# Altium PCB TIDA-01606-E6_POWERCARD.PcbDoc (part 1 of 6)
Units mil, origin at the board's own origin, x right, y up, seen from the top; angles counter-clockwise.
Board outline 13779.53 x 7874.02 mil, 4 copper layers (Top Layer, Gnd Layer, Pwr Layer, Bottom Layer), stack 94.4 mil thick; 550 components, 292 nets, 1594 pads, 572 vias.
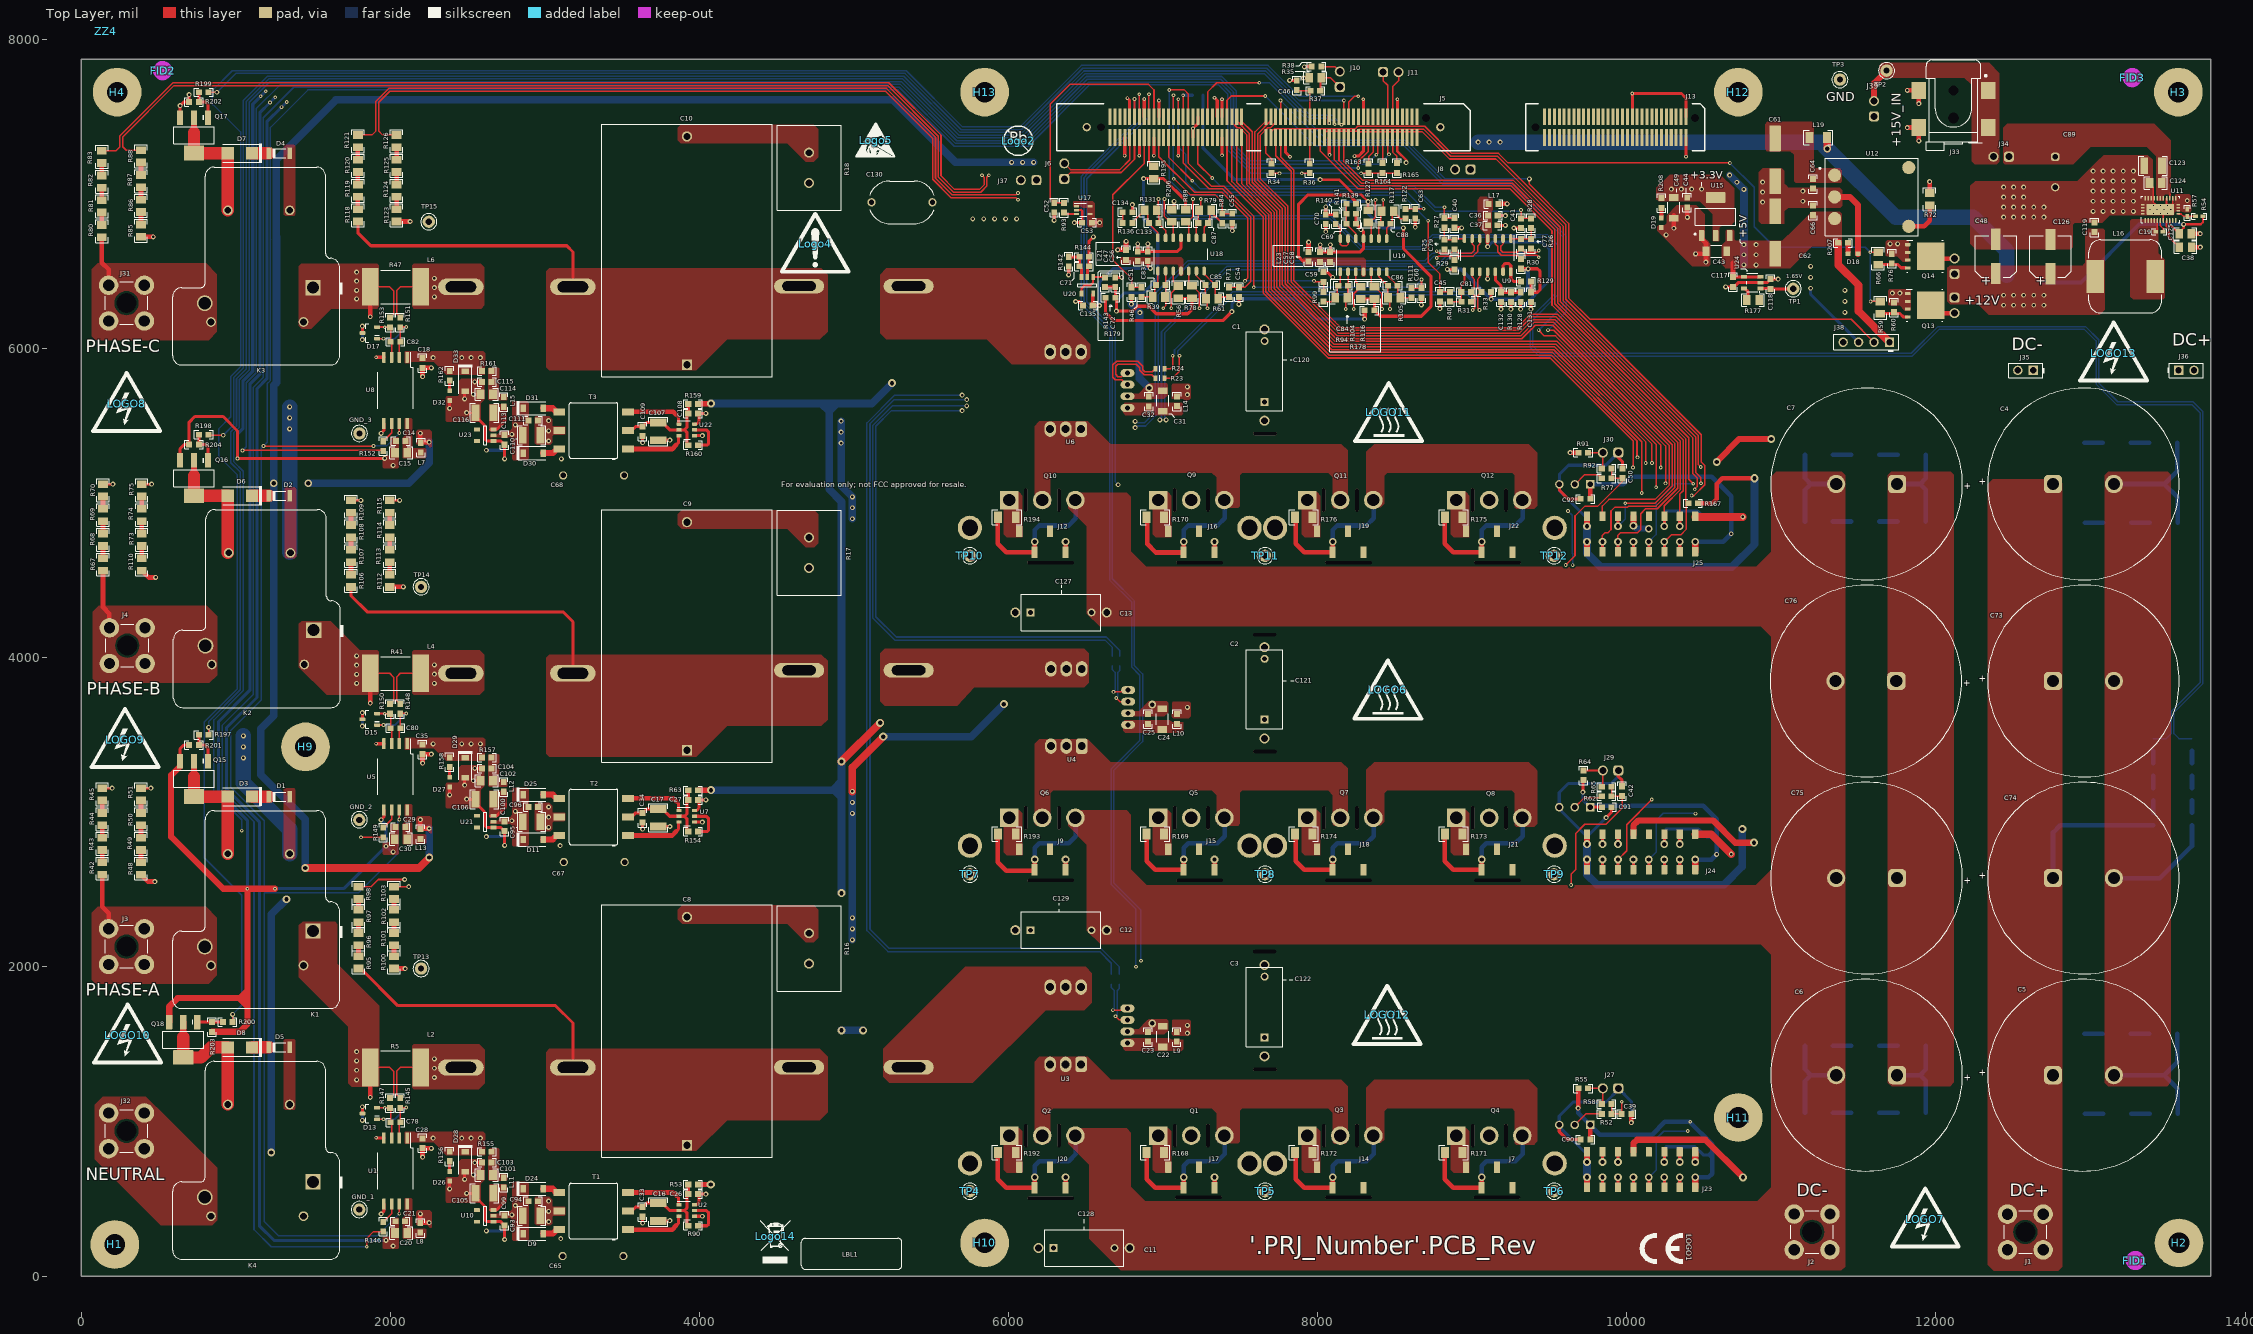
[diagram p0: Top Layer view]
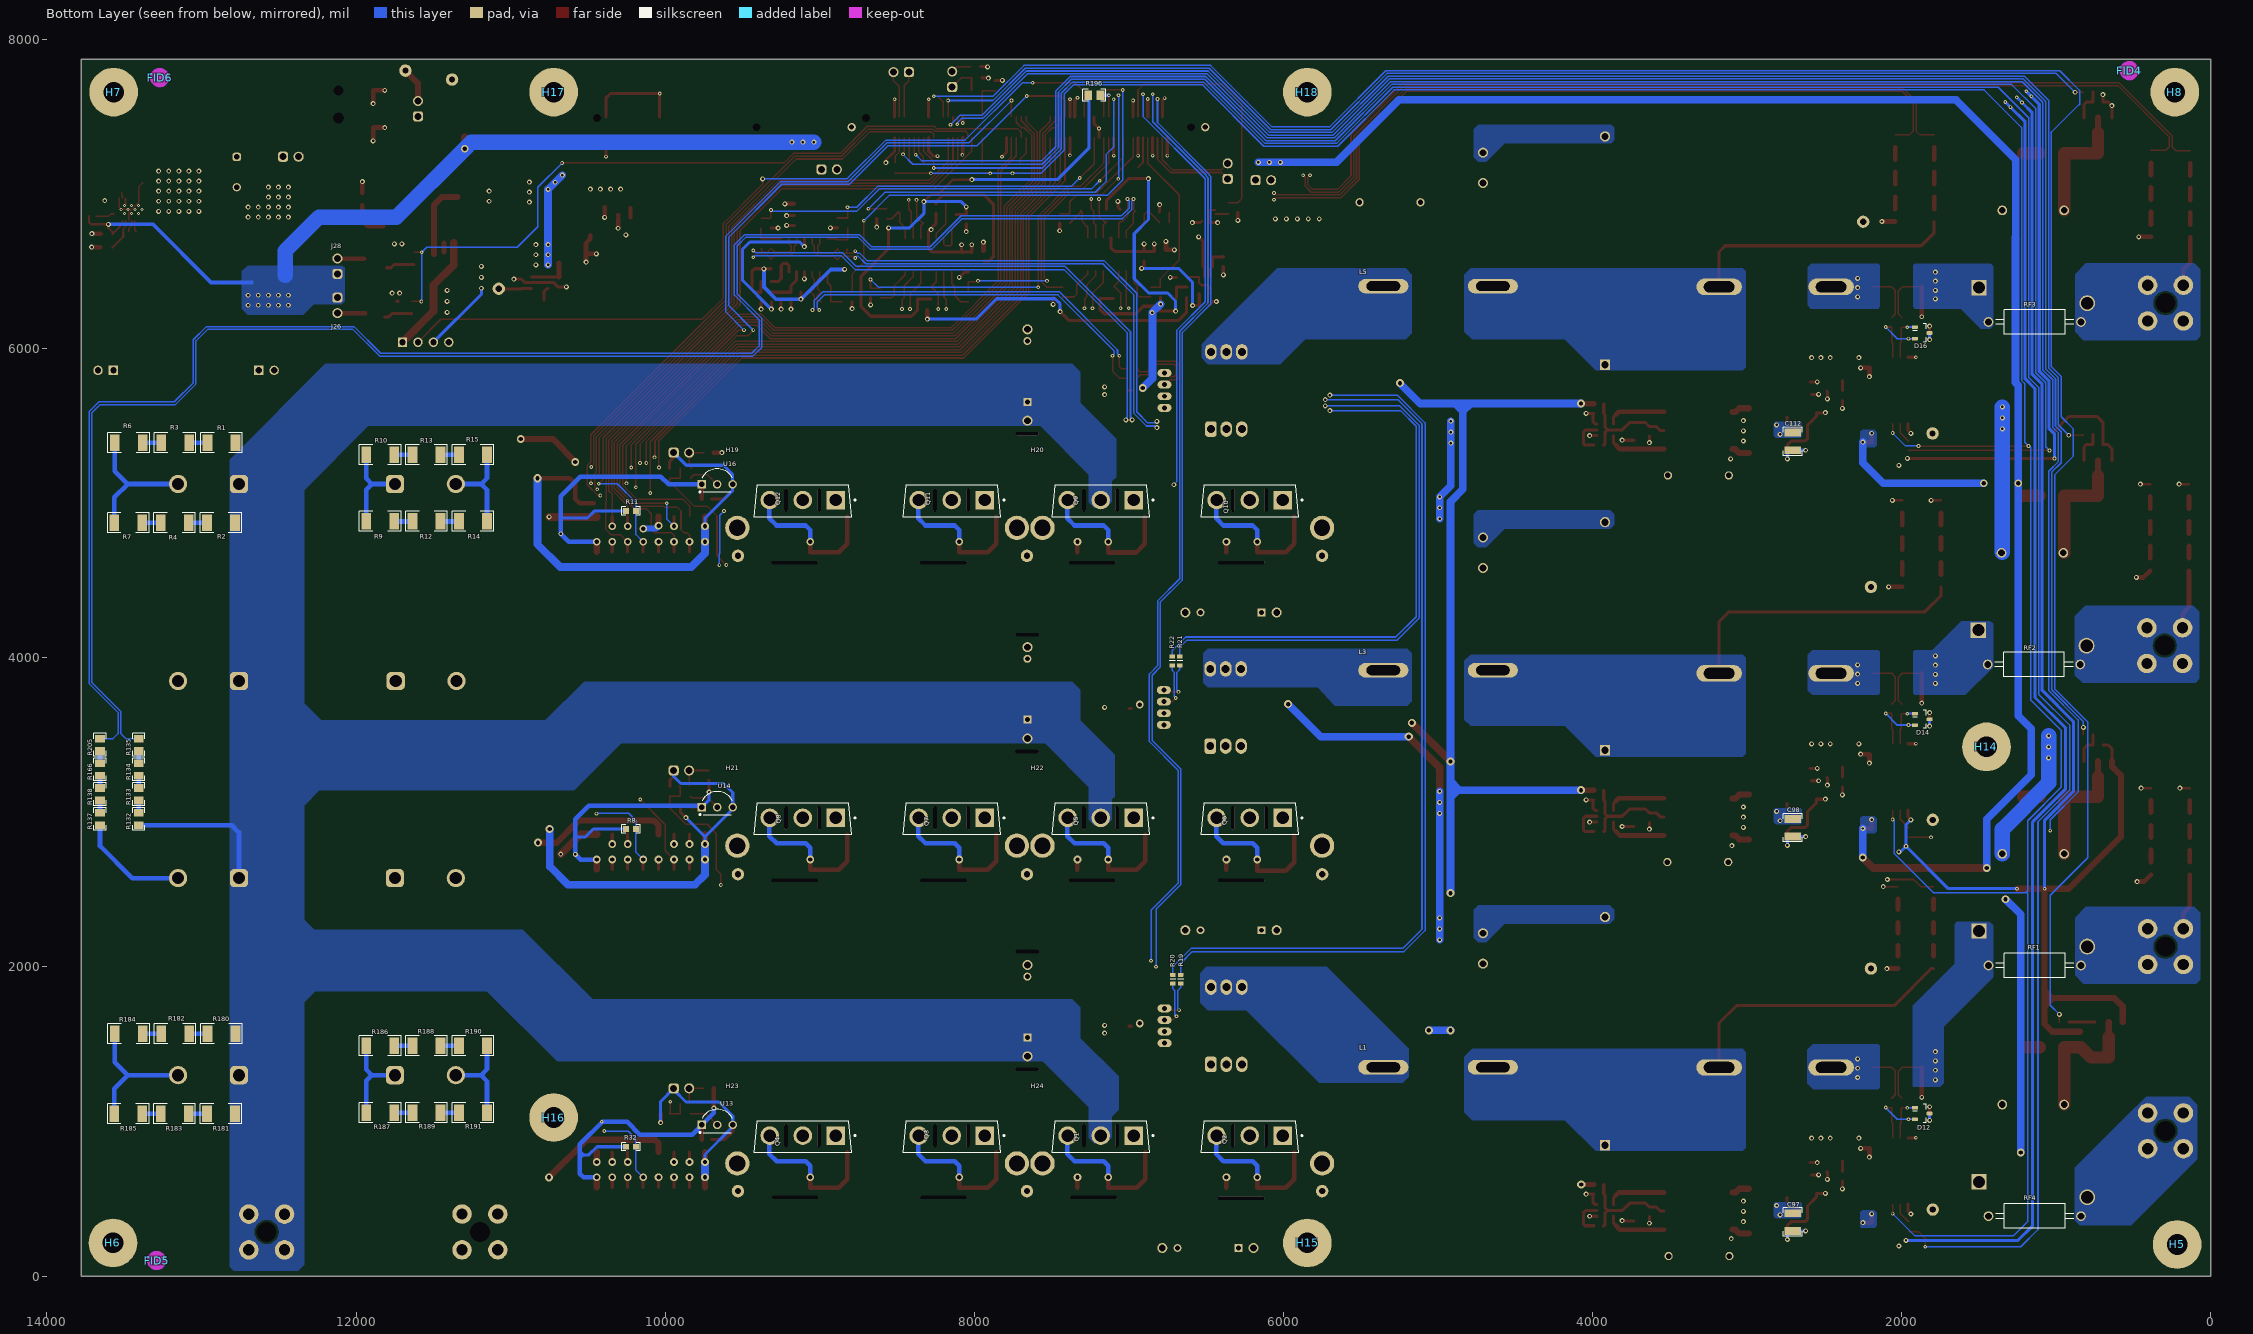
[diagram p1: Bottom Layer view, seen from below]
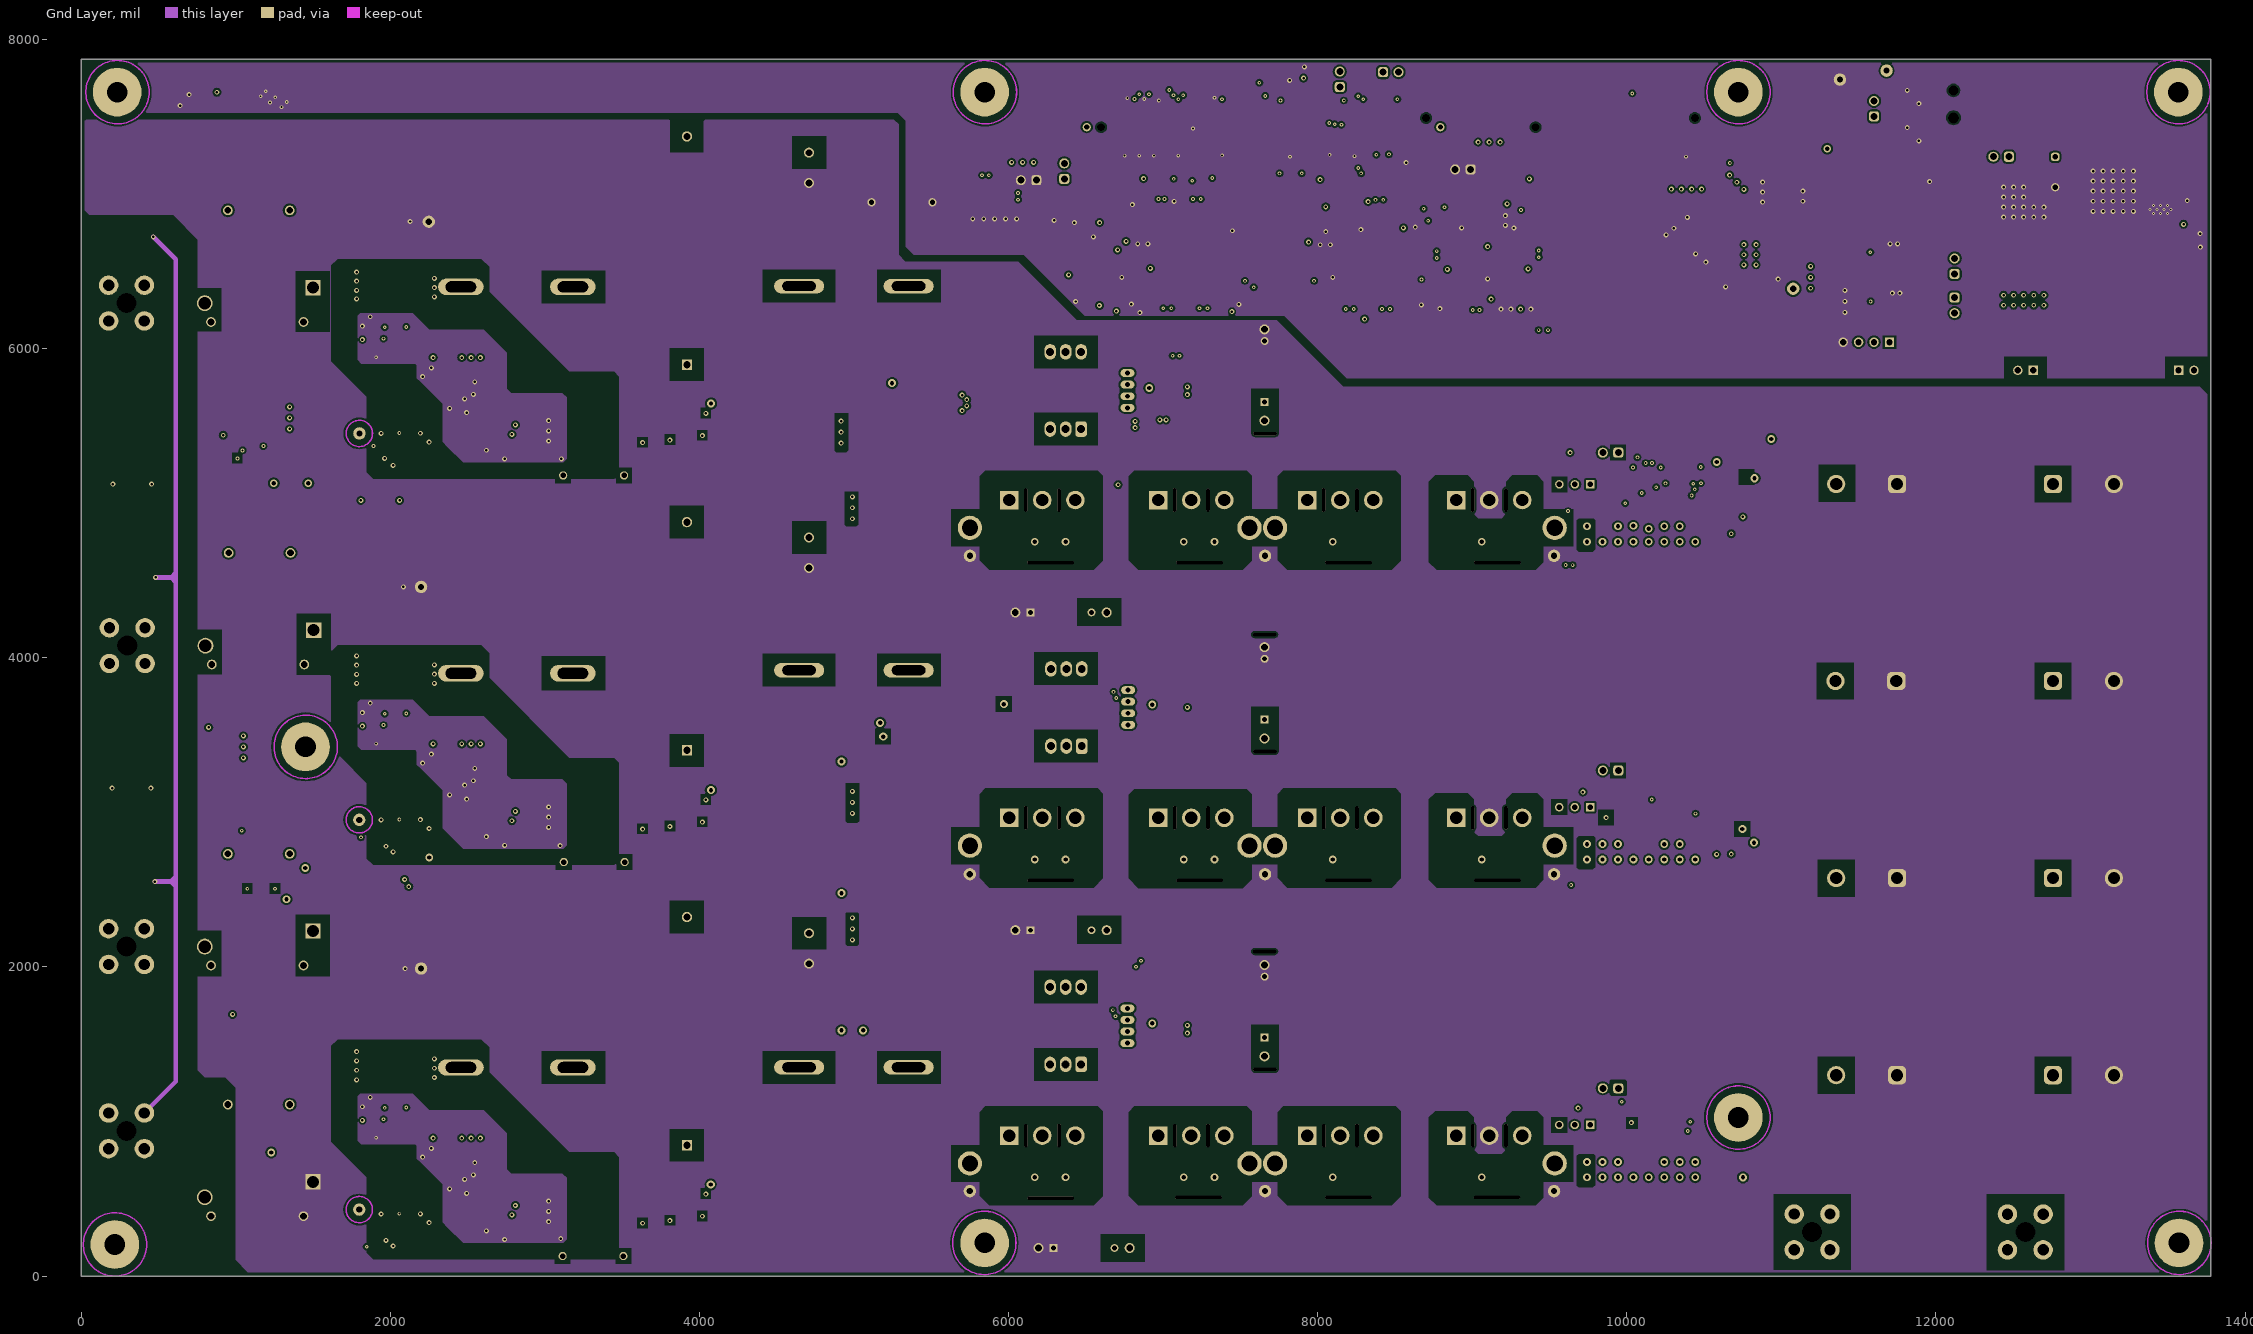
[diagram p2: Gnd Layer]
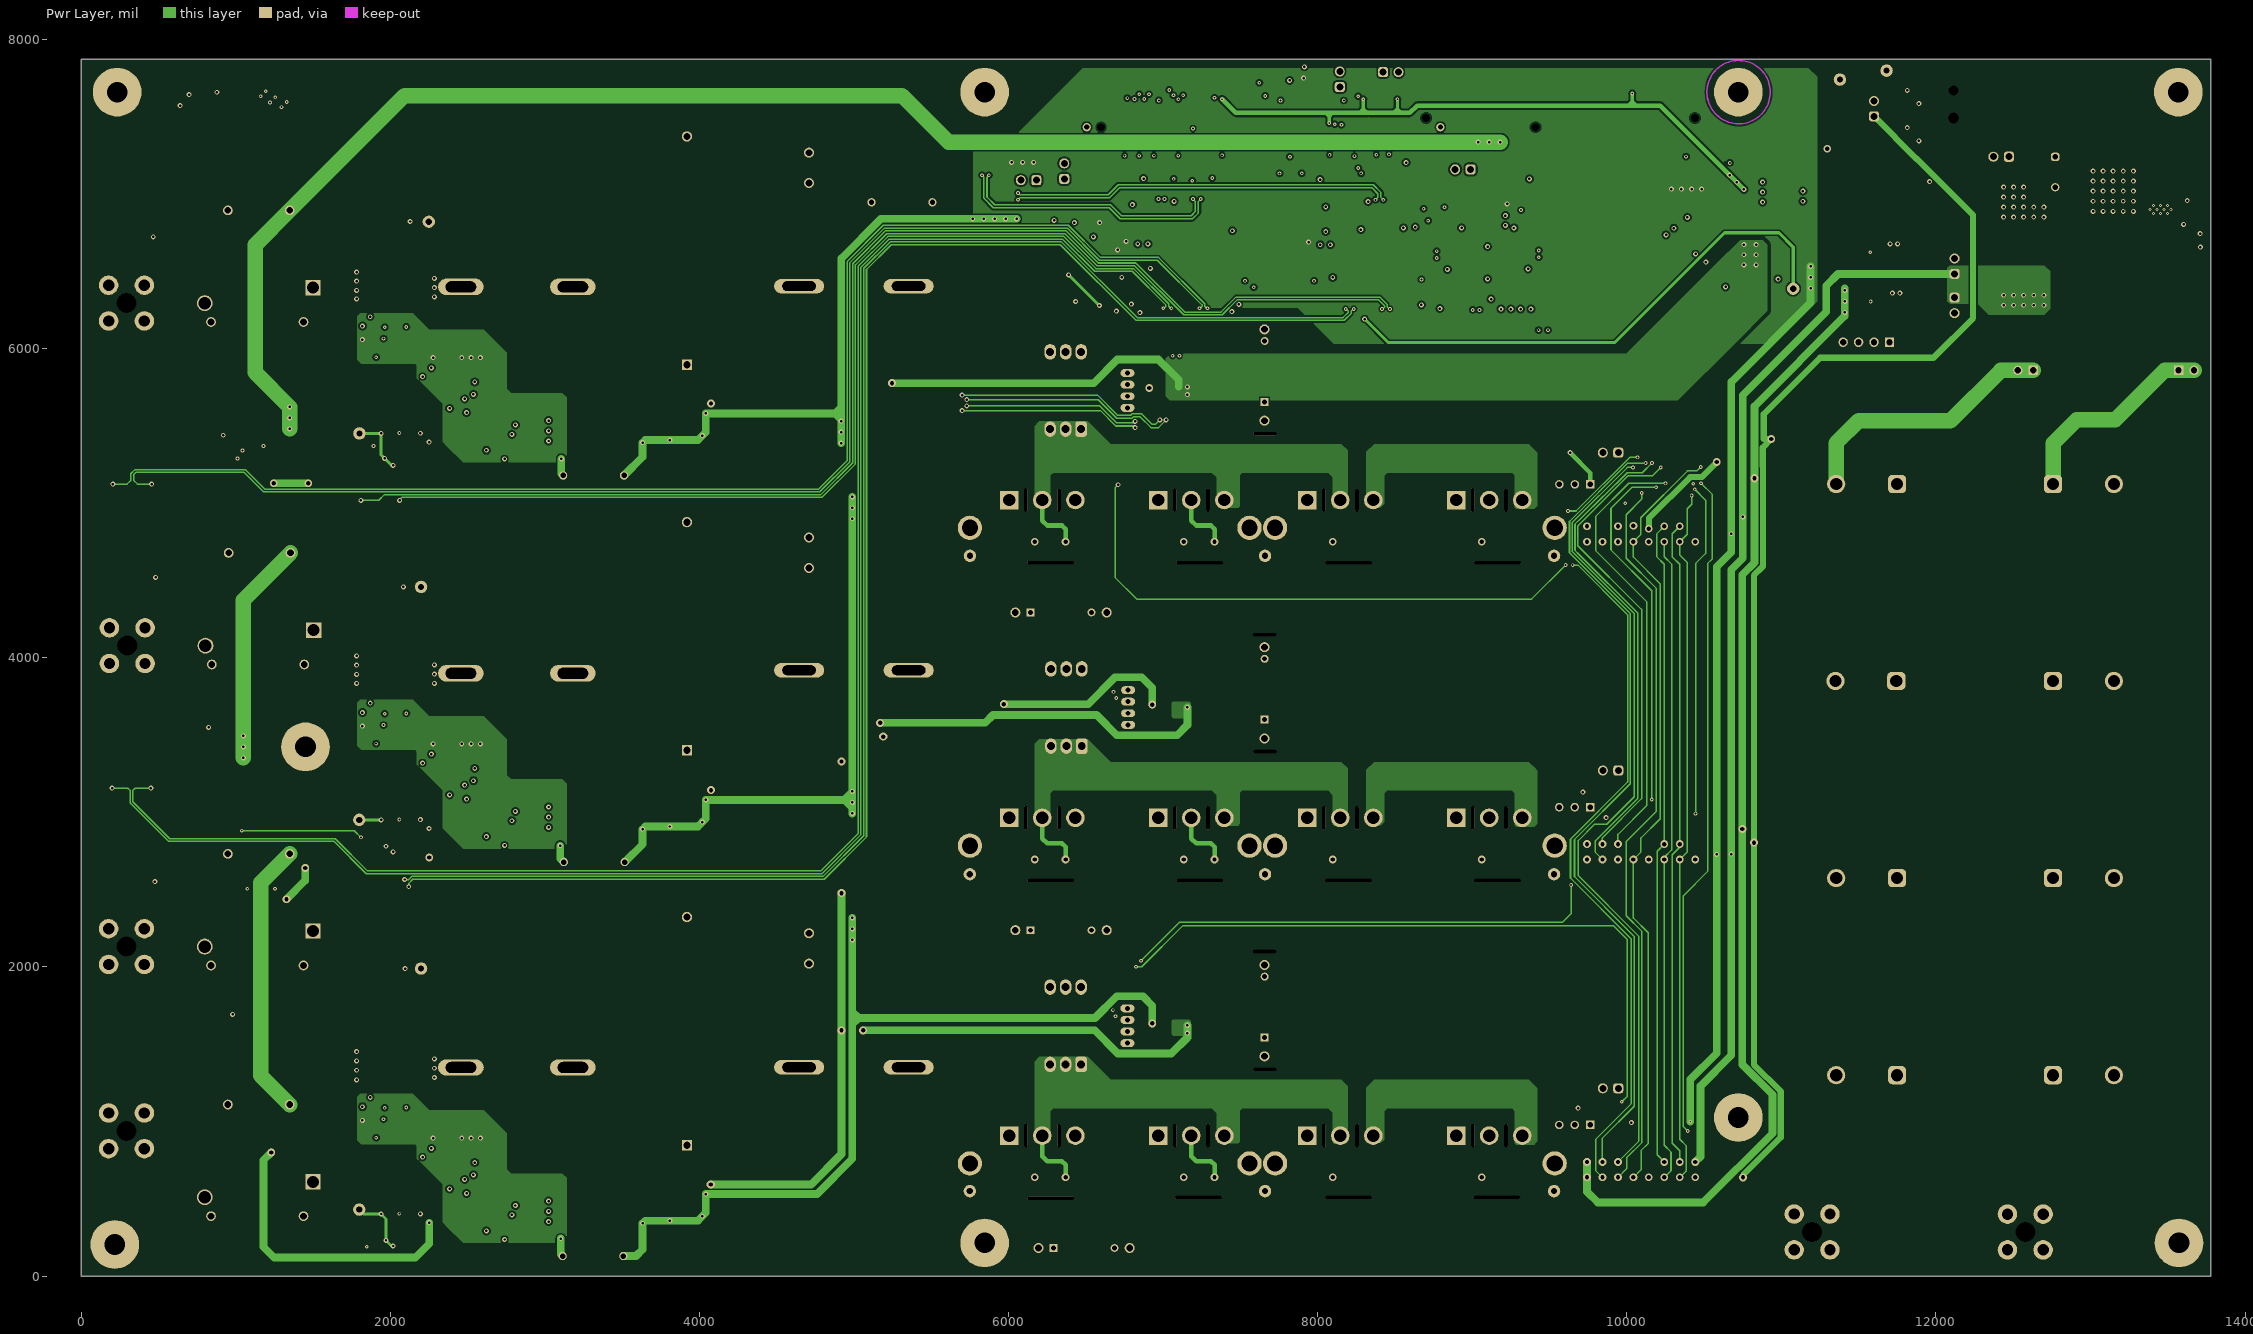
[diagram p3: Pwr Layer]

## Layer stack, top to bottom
Top Solder: solder mask 0.4, Solder Resist, Dk 3.5
Top Layer: signal copper 2.8
Dielectric 1: dielectric 12, FR-4-High Tg, Dk 4.2
Gnd Layer: signal copper 2.8
Dielectric2: core 59.2, FR-4-High Tg, Dk 4.2
Pwr Layer: signal copper 2.8
Dielectric 3: dielectric 12, FR-4-High Tg, Dk 4.2
Bottom Layer: signal copper 2.8
Bottom Solder: solder mask 0.4, Solder Resist, Dk 3.5

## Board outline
0,0 13779.53,0 13779.53,7874.02 0,7874.02

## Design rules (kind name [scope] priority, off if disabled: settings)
AcuteAngle [All] p1: minimum=4.50000000000000E+0001 checktracksonly=FALSE
AssemblyTestPointUsage [All] p1: valid=2
BoardOutlineClearance BoardOutlineClearance_MountingHoles [OnCopper and InComponentClass('Mounting Holes')] p1: gap=40 ignorepadtopadclearanceinfootprint=FALSE
BoardOutlineClearance BoardOutlineClearance_Poly [OnCopper and IsPoly] p2: gap=25 ignorepadtopadclearanceinfootprint=FALSE
BoardOutlineClearance [OnCopper and Not InComponentClass('Logo') and not InComponentClass('FiducialMark') and not InRegion(1000,500,4000,800) and not InPoly] p3: gap=0 ignorepadtopadclearanceinfootprint=FALSE
Clearance Clearance_MH [InPadClass('mh')] p1: gap=59.06 ignorepadtopadclearanceinfootprint=FALSE except(0: Arc-Hole Track-Hole SMDPad-Hole THPad-Hole Via-Hole Fill-Hole Poly-Hole Region-Hole Text-Hole)
Clearance Clearance_HV_Bottom_Layer [InLayerClass('Bottom_Layer') and InPolygon vs InNetClass('HV_Class')] p2: gap=118.11 ignorepadtopadclearanceinfootprint=FALSE except(0: Arc-Hole Track-Hole SMDPad-Hole THPad-Hole Via-Hole Fill-Hole Poly-Hole Region-Hole Text-Hole)
Clearance Clearance_HV_TOP_Layer [InLayerClass('Top_Layer') and InPolygon vs InNetClass('HV_Class')] p3: gap=118.11 ignorepadtopadclearanceinfootprint=FALSE except(0: Arc-Hole Track-Hole SMDPad-Hole THPad-Hole Via-Hole Fill-Hole Poly-Hole Region-Hole Text-Hole)
Clearance Clearance_HV_PwrLayer [InLayerClass('PWR Class') and InPolygon vs InNetClass('HV_Class')] p4: gap=118.11 ignorepadtopadclearanceinfootprint=FALSE except(0: Arc-Hole Track-Hole SMDPad-Hole THPad-Hole Via-Hole Fill-Hole Poly-Hole Region-Hole Text-Hole)
Clearance Clearance_HV_GndLayer [InLayerClass('GND_Layer') and InPolygon vs InNetClass('HV_Class')] p5: gap=60 ignorepadtopadclearanceinfootprint=FALSE except(0: Arc-Hole Track-Hole SMDPad-Hole THPad-Hole Via-Hole Fill-Hole Poly-Hole Region-Hole Text-Hole)
Clearance "Clearance_Poly to Poly" [InPoly vs InPoly] p6: gap=25 ignorepadtopadclearanceinfootprint=FALSE except(0: Arc-Hole Track-Hole SMDPad-Hole THPad-Hole Via-Hole Fill-Hole Poly-Hole Region-Hole Text-Hole)
Clearance Clearance_Poly [InPolygon] p7: gap=12 ignorepadtopadclearanceinfootprint=FALSE except(0: Arc-Hole Track-Hole SMDPad-Hole THPad-Hole Via-Hole Fill-Hole Poly-Hole Region-Hole Text-Hole)
Clearance [All] p8: gap=7.87 ignorepadtopadclearanceinfootprint=FALSE except(0: Arc-Hole Track-Hole SMDPad-Hole THPad-Hole Via-Hole Fill-Hole Poly-Hole Region-Hole Text-Hole)
ComponentClearance ComponentClearance_MountingHoles_FiducialMarks [InComponentClass('Mounting Holes') vs InComponentClass('FiducialMark')] p1: gap=30 collisioncheckmode=3 verticalgap=10 showdistances=FALSE
ComponentClearance ComponentClearance_Shunt [InComponentClass('Header') vs InComponentClass('Shunt')] p2: gap=0 collisioncheckmode=3 verticalgap=0 showdistances=FALSE
ComponentClearance ComponentClearance_Logo [InComponentClass('Logo')] p3: gap=1 collisioncheckmode=3 verticalgap=1 showdistances=FALSE
ComponentClearance ComponentClearance_ScrewToNut [(HasFootprint('NY PMS 440 0025 PH')) vs (HasFootprint('Keystone_1902C'))] p4: gap=1 collisioncheckmode=3 verticalgap=1 showdistances=FALSE
ComponentClearance ComponentClearance_MountingHoles [InComponentClass('Mounting Holes')] p5: gap=30 collisioncheckmode=3 verticalgap=100000 showdistances=FALSE
ComponentClearance ComponentClearance_SmallPassives [HasFootprint('0201*') or HasFootprint('0402*') or HasFootprint('0508') or HasFootprint('0603*') or HasFootprint('0612') or HasFootprint('0805*') or HasFootprint('0815*') or HasFootprint('0830*') or HasFootprint('1206*') or HasFootprint('1210*') or HasFootprint('1808*') or HasFootprint('1812*') or HasFootprint('1825*') or HasFootprint('2010*') or HasFootprint('2220*') or HasFootprint('2225*') or HasFootprint('2512*') or HasFootprint('2728*') or HasFootprint('3518*') vs HasFootprint('0201*') or HasFootprint('0402*') or HasFootprint('0508') or HasFootprint('0603*') or HasFootprint('0612') or HasFootprint('0805*') or HasFootprint('0815*') or HasFootprint('0830*') or HasFootprint('1206*') or HasFootprint('1210*') or HasFootprint('1808*') or HasFootprint('1812*') or HasFootprint('1825*') or HasFootprint('2010*') or HasFootprint('2220*') or HasFootprint('2225*') or HasFootprint('2512*') or HasFootprint('2728*') or HasFootprint('3518*')] p6: gap=0 collisioncheckmode=3 verticalgap=0 showdistances=FALSE
ComponentClearance ComponentClearance_THtoSMT [IsThruComponent vs IsSMTComponent] p7: gap=0 collisioncheckmode=3 verticalgap=0 showdistances=FALSE
ComponentClearance ComponentClearance_THtoTH [IsThruComponent vs IsThruComponent] p8: gap=0 collisioncheckmode=3 verticalgap=0 showdistances=FALSE
ComponentClearance [All] p9: gap=0 collisioncheckmode=3 verticalgap=0 showdistances=FALSE
DiffPairsRouting [All] p1: maxlimit=10 minlimit=7.87 mostfreqgap=7.87 toplayer_minwidth=10 toplayer_maxwidth=10 toplayer_prefwidth=10 midlayer1_minwidth=10 midlayer1_maxwidth=10 midlayer1_prefwidth=10 midlayer2_minwidth=10 midlayer2_maxwidth=10 midlayer2_prefwidth=10 bottomlayer_minwidth=10 bottomlayer_maxwidth=10 bottomlayer_prefwidth=10 maxuncoupledlength=1000
FabricationTestPointUsage TestPointUsage [All] p1: valid=2 allowmultiple=FALSE
FabricationTestpoint Testpoint [All] p1: side=3 testpointundercomponent=TRUE minsize=40 maxsize=100 preferedsize=60 minholesize=0 maxholesize=40 preferedholesize=32 testpointgrid=1 allowsidetop=TRUE allowsidebottom=TRUE usegrid=TRUE gridtolerance=0.01
FanoutControl Fanout_LCC [IsLCC] p1: bgadir=Out bgaviamode=Centered fanoutstyle=Auto fanoutdirection=Alternating viagrid=1 // Fanout_LCC (Default Rule)
FanoutControl Fanout_BGA [IsBGA] p2: bgadir=Out bgaviamode=Centered fanoutstyle=Auto fanoutdirection=Alternating viagrid=1 // Fanout_BGA (Default Rule)
FanoutControl Fanout_Default [All] p4: bgadir=Out bgaviamode=Centered fanoutstyle=Auto fanoutdirection=Alternating viagrid=1 // Fanout_Default (Default Rule)
FanoutControl Fanout_Small [(CompPinCount < 5)] p5: bgadir=Out bgaviamode=Centered fanoutstyle=Auto fanoutdirection=OutThenIn viagrid=1 // Fanout_Small (Default Rule)
Height [All] p1: minheight=0 maxheight=2500 prefheight=500
HoleSize [All] p1: absolutevalues=TRUE maxlimit=1000 minlimit=7.87 maxpercent=80.000 minpercent=20.000
MinimumAnnularRing MinimumAnnularRing_ThermalPadVias [IsVia and InAnyComponent] p1: minimumring=5.91
MinimumAnnularRing [All] p2: minimumring=5.5
MinimumSolderMaskSliver MinimumSolderMaskSliver_Logo [InComponentClass('Logo') vs InComponentClass('Logo')] p1: minsoldermaskwidth=0.7
MinimumSolderMaskSliver [All] p2: minsoldermaskwidth=3.94
PlaneConnect [All] p1: planeconnectstyle=Direct reliefexpansion=10 reliefentries=4 reliefconductorwidth=10 reliefairgap=10
PolygonConnect [All] p1: connectstyle=Direct reliefconductorwidth=10 reliefentries=4 polygonreliefangle="90 Angle" airgapwidth=10
RoutingVias ThermalPadVias [IsVia and InAnyComponent] p1: holewidth=7.87 width=19.68 viastyle="Through Hole" minholewidth=7.87 minwidth=19.68 maxholewidth=12.99 maxwidth=23.62
RoutingVias [All] p2: holewidth=16 width=32 viastyle="Through Hole" minholewidth=12 minwidth=24 maxholewidth=28 maxwidth=52
SilkToBoardRegionClearance [Not ((IsComment or IsDesignator) And (Hide <> 'False')) and not InRegion(1000,500,4000,800)] p1:
SilkToSilkClearance SilkToSilkClearance_Pb-FreeLogo [(HasFootprint('Pb-Free_Overlay_Medium') OR HasFootprint('Pb-Free_Overlay_Small')) vs (HasFootprint('Pb-Free_Overlay_Medium') OR HasFootprint('Pb-Free_Overlay_Small'))] p1: silktosilkclearance=0
SilkToSilkClearance [All] p2: silktosilkclearance=4
SilkToSolderMaskClearance SilkToComponentPadClearance [(IsPad or IsFill or IsRegion) and InAnycomponent] p1: minsilkscreentomaskgap=5 clearancetoexposedcopper=TRUE
SilkToSolderMaskClearance "Silk to Solder Mask Opening" [All] p2: minsilkscreentomaskgap=4 clearancetoexposedcopper=FALSE
SolderMaskExpansion [All] p1: expansion=1.97 istentingtop=FALSE
Width [All] p1: maxlimit=100 minlimit=9 preferedwidth=40 checkconnectedcopper=TRUE
14 further rules are at their usual default settings.

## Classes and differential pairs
component class "TIDA-01606-E6_POWERCARD_Power Supply and Protection_Pg3": C16 C17 C19 C26 C27 C33 C34 C38 C39 C42 C43 C44 C48 C49 C50 C52 C53 C61 C62 C64 C65 C66 C67 C68 C89 C90 C91 C92 C93 C94 C95 C96 C97 C98 C99 C100 C101 C102 C103 C104 C105 C106 C107 C108 C109 C110 C111 C112 C113 C114 C115 C116 C119 C123 C124 C125 C126 D9 D11 D18 D19 D24 D25 D26 D27 D28 D29 D30 D31 D32 D33 J27 J29 J30 J33 J34 J39 L11 L12 L15 L16 L19 R52 R53 R54 R55 R57 R58 R62 R63 R64 R65 R72 R77 R90 R91 R92 R93 R154 R155 R156 R157 R158 R159 R160 R161 R162 R207 R208 T1 T2 T3 U2 U7 U10 U11 U12 U13 U14 U15 U16 U17 U21 U22 U23
component class Screw: H1 H2 H3 H4 H9 H10 H11 H12 H13
component class TIDA-01606-E6_POWERCARD_Hardware_Pg7: FID1 FID2 FID3 FID4 FID5 FID6 H1 H2 H3 H4 H5 H6 H7 H8 H9 H10 H11 H12 H13 H14 H15 H16 H17 H18 LBL1 LOGO1 Logo2 Logo3 Logo4 Logo5 LOGO6 LOGO7 LOGO8 LOGO9 LOGO10 LOGO11 LOGO12 LOGO13 Logo14 ZZ1 ZZ2 ZZ3 ZZ4
component class FiducialMark: FID1 FID2 FID3 FID4 FID5 FID6
component class AssemblyNote: ZZ1 ZZ2 ZZ3 ZZ4
component class Label: LBL1
component class "TIDA-01606-E6_POWERCARD_Power Stage_Pg2": C1 C2 C3 C4 C5 C6 C7 C8 C9 C10 C11 C12 C13 C73 C74 C75 C76 C120 C121 C122 C127 C128 C129 C130 D1 D2 D3 D4 D5 D6 D7 D8 H19 H20 H21 H22 H23 H24 J1 J2 J3 J4 J31 J32 J35 J36 K1 K2 K3 K4 L1 L2 L3 L4 L5 L6 Q1 Q2 Q3 Q4 Q5 Q6 Q7 Q8 Q9 Q10 Q11 Q12 Q15 Q16 Q17 Q18 R1 R2 R3 R4 R5 R6 R7 R9 R10 R12 R13 R14 R15 R16 R17 R18 R41 R47 R168 R169 R170 R171 R172 R173 R174 R175 R176 R180 R181 R182 R183 R184 R185 R186 R187 R188 R189 R190 R191 R192 R193 R194 R197 R198 R199 R200 R201 R202 R203 R204 RF1 RF2 RF3 RF4 TP2 TP3 TP4 TP5 TP6 TP7 TP8 TP9 TP10 TP11 TP12 TP13 TP14 TP15
component class "TIDA-01606-E6_POWERCARD_Current Sensing_Pg5": C14 C15 C18 C20 C21 C22 C23 C24 C25 C28 C29 C30 C31 C32 C35 C36 C37 C40 C41 C45 C77 C78 C79 C80 C81 C82 C131 C132 D12 D13 D14 D15 D16 D17 GND_1 GND_2 GND_3 L7 L8 L9 L10 L13 L14 L17 R19 R20 R21 R22 R23 R24 R25 R26 R27 R28 R29 R30 R31 R33 R40 R128 R129 R130 R145 R146 R147 R148 R149 R150 R151 R152 R153 U1 U3 U4 U5 U6 U8 U9
component class "TIDA-01606-E6_POWERCARD_Controller Card_Pg6": C46 C117 C118 J5 J6 J7 J8 J9 J10 J11 J12 J13 J14 J15 J16 J17 J18 J19 J20 J21 J22 J23 J24 J25 J26 J28 J37 J38 Q13 Q14 R8 R11 R32 R34 R35 R36 R37 R38 R59 R60 R66 R76 R163 R164 R165 R167 R177 R195 R196 TP1 U24
component class "TIDA-01606-E6_POWERCARD_Voltage Sensing_Pg4": C47 C51 C54 C55 C56 C57 C58 C59 C60 C63 C69 C70 C71 C72 C83 C84 C85 C86 C87 C88 C133 C134 C135 L21 L23 R39 R42 R43 R44 R45 R46 R48 R49 R50 R51 R56 R61 R67 R68 R69 R70 R71 R73 R74 R75 R78 R79 R80 R81 R82 R83 R84 R85 R86 R87 R88 R89 R94 R95 R96 R97 R98 R99 R100 R101 R102 R103 R104 R105 R106 R107 R108 R109 R110 R111 R112 R113 R114 R115 R116 R117 R118 R119 R120 R121 R122 R123 R124 R125 R126 R127 R131 R132 R133 R134 R135 R136 R137 R138 R139 R140 R141 R142 R143 R144 R166 R178 R179 R205 R206 U18 U19 U20
component class Header: J6 J8 J10 J11 J26 J27 J28 J29 J30 J34 J37 J39
pad class mh: H1-1 H2-1 H3-1 H4-1 H9-1 H10-1 H11-1 H12-1 H13-1
differential pair PD: +PD_P -PD_N
differential pair VC: +VC_P -VC_N
differential pair VB: +VB_P -VB_N
differential pair VA: +VA_P -VA_N
differential pair PC: +PC_P -PC_N
differential pair PB: +PB_P -PB_N
differential pair PA: +PA_P -PA_N
differential pair ILC: +ILC_P -ILC_N
differential pair ILB: +ILB_P -ILB_N
differential pair ILA: +ILA_P -ILA_N

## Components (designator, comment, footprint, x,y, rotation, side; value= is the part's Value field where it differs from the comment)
C1 "890303325008CS" WCAP-FTBP_1800x700x1300 7656.99,5829.8 r90 top value=0.15uF
C2 "890303325008CS" WCAP-FTBP_1800x700x1300 7656.99,3773.73 r90 top value=0.15uF
C3 "890303325008CS" WCAP-FTBP_1800x700x1300 7656.99,1717.67 r90 top value=0.15uF
C4 "LGN2X121MELB45" Nichicon_3000x4500_Snap 12954.7,5124.48 r0 top value=120uF
C5 "LGN2X121MELB45" Nichicon_3000x4500_Snap 12954.7,1300 r0 top value=120uF
C6 "LGN2X121MELB45" Nichicon_3000x4500_Snap 11551.85,1300 r180 top value=120uF
C7 "LGN2X121MELB45" Nichicon_3000x4500_Snap 11551.85,5124.48 r180 top value=120uF
C8 "B32926C3106K000" B32926_42.5mm 3920,1585 r90 top locked value=10uF
C9 "B32926C3106K000" B32926_42.5mm 3920,4140 r90 top locked value=10uF
C10 "B32926C3106K000" B32926_42.5mm 3920,6635 r90 top locked value=10uF
C11 "890303325008CS" WCAP-FTBP_1800x700x1300 6489.02,181.87 r0 top value=0.15uF
C12 "890303325008CS" WCAP-FTBP_1800x700x1300 6340.02,2237.93 r0 top value=0.15uF
C13 "890303325008CS" WCAP-FTBP_1800x700x1300 6340.02,4293.99 r0 top value=0.15uF
C14 "C0603X104K3RACTU" 0603 2068.45,5402.4 r0 top value=0.1uF
C15 "GRM216R61A225KE24D" 0805_HV 2071,5327 r180 top value=2.2uF
C16 "GRM32ER7YA106KA12L" 1210_270 3734,415 r90 top value=10uF
C17 "GRM32ER7YA106KA12L" 1210_270 3734,2965 r90 top value=10uF
C18 "C0603X104K3RACTU" 0603 2209.45,5908.03 r270 top value=0.1uF
C19 "GRM155R60J474KE19D" 0402 13446,6757 r0 top value=0.47uF
C20 "GRM216R61A225KE24D" 0805_HV 2071,279 r180 top value=2.2uF
C21 "C0603X104K3RACTU" 0603 2065,355 r0 top value=0.1uF
C22 "C3216X7R1E106K160AB" 1206_180 6998.08,1549.73 r90 top value=10uF
C23 "C0603X104K3RACTU" 0603 6903.08,1548.21 r90 top value=0.1uF
C24 "C3216X7R1E106K160AB" 1206_180 6995.08,3603.8 r90 top value=10uF
C25 "C0603X104K3RACTU" 0603 6903.08,3604.28 r90 top value=0.1uF
C26 "C0603C104K5RACAUTO" 0603 3960,531 r180 top value=0.1uF
C27 "C0603C104K5RACAUTO" 0603 3960,3081 r180 top value=0.1uF
C28 "C0603X104K3RACTU" 0603 2209.45,860 r270 top value=0.1uF
C29 "C0603X104K3RACTU" 0603 2067,2905 r0 top value=0.1uF
C30 "GRM216R61A225KE24D" 0805_HV 2070,2827 r180 top value=2.2uF
C31 "C3216X7R1E106K160AB" 1206_180 6998.08,5661.86 r90 top value=10uF
C32 "C0603X104K3RACTU" 0603 6908.08,5658.86 r90 top value=0.1uF
C33 "C0603C104K5RACAUTO" 0603 3633,415.5 r90 top value=0.1uF
C34 "C0603C104K5RACAUTO" 0603 3633,2965.5 r90 top value=0.1uF
C35 "C0603X104K3RACTU" 0603 2209.45,3408.03 r270 top value=0.1uF
C36 "C0603X104K3RACTU" 0603 9133.7,6861.17 r180 top value=0.1uF
C37 "C0603C105K3RACTU" 0603 9132.7,6798.17 r0 top value=1uF
C38 "GRM216R61A225KE24D" 0805_HV 13615,6657 r0 top value=2.2uF
C39 "C0603X104K3RACTU" 0603 9998.5,1049 r180 top value=0.1uF
C40 "C0603X104K3RACTU" 0603 8885.7,6814 r90 top value=0.1uF
C41 "C0603X104K3RACTU" 0603 9316,6812 r90 top value=0.1uF
C42 "C0603X104K3RACTU" 0603 9970,3137.89 r270 top value=0.1uF
C43 "C3216X7R1E106K160AB" 1206_180 10579.7,6630.19 r180 top value=10uF
C44 "C0603X104K3RACTU" 0603 10391,6946 r270 top value=0.1uF
C45 "C0603X104K3RACTU" 0603 8791,6336.27 r90 top value=0.1uF
C46 "C0603X104K3RACTU" 0603 7865.63,7704 r270 top value=0.1uF
C47 "C0603X104K3RACTU" 0603 6837.05,6598.17 r270 top value=0.1uF
C48 "875105444004" WCAP-PSLP_630x580 12388,6597 r90 top value=33uF
C49 "C3216X7R1E106K160AB" 1206_180 10304,6911 r270 top value=10uF
C50 "C0603X104K3RACTU" 0603 9972,5193.5 r270 top value=0.1uF
C51 "C0603X104K3RACTU" 0603 6796.11,6366 r90 top value=0.1uF
C52 "C0603X104K3RACTU" 0603 6296,6912.55 r90 top value=0.1uF
C53 "C0603X104K3RACTU" 0603 6507.8,6815.55 r0 top value=0.1uF
C54 "C0603X104K3RACTU" 0603 7491.11,6366 r90 top value=0.1uF
C55 "C0603X104K3RACTU" 0603 7448,6843 r90 top value=0.1uF
C56 "C0603C105K3RACTU" 0603 6901.54,6598.17 r90 top value=1uF
C57 "C0603X104K3RACTU" 0603 8015.83,6593.17 r270 top value=0.1uF
C58 "C0603C105K3RACTU" 0603 8080.83,6593.17 r90 top value=1uF
C59 "C0603X104K3RACTU" 0603 8038.3,6464 r270 top value=0.1uF
C60 "C0603X104K3RACTU" 0603 8671.7,6361 r90 top value=0.1uF
C61 "865060653010" WCAP-ASLL_800x1050 10959.7,7222 r270 top value=100uF
C62 "865060653010" WCAP-ASLL_800x1050 10959.7,6752 r90 top value=100uF
C63 "C0603X104K3RACTU" 0603 8631.7,6873 r90 top value=0.1uF
C64 "C0603C104K5RACAUTO" 0603 11204.7,7067 r270 top value=0.1uF
C65 "VY1102M35Y5UQ63V0" VY1_900x500x1300 3312.13,130 r0 top value=1000pF
C66 "C0603C104K5RACAUTO" 0603 11205,6895 r90 top value=0.1uF
C67 "VY1102M35Y5UQ63V0" VY1_900x500x1300 3320,2678.91 r0 top value=1000pF
C68 "VY1102M35Y5UQ63V0" VY1_900x500x1300 3316,5180 r0 top value=1000pF
C69 "C0603X104K3RACTU" 0603 8217.7,6808 r180 top value=0.1uF
C70 "C0603X104K3RACTU" 0603 8052.7,6838 r90 top value=0.1uF
C71 "C0603X104K3RACTU" 0603 6490,6533 r180 top value=0.1uF
C72 "C0603X104K3RACTU" 0603 6691.5,6430 r270 top value=0.1uF
C73 "LGN2X121MELB45" Nichicon_3000x4500_Snap 12954.7,3850 r0 top value=120uF
C74 "LGN2X121MELB45" Nichicon_3000x4500_Snap 12954.7,2575 r0 top value=120uF
C75 "LGN2X121MELB45" Nichicon_3000x4500_Snap 11551.85,2575 r180 top value=120uF
C76 "LGN2X121MELB45" Nichicon_3000x4500_Snap 11546.85,3850 r180 top value=120uF
C77 "CL10B101KB8NNNC" 0603 9315.7,6679 r270 top value=100pF
C78 "06035A820JAT2A" 0603 2034.45,995 r180 top value=82pF
C79 "CL10B101KB8NNNC" 0603 8885.7,6674 r270 top value=100pF
C80 "06035A820JAT2A" 0603 2034.45,3545 r180 top value=82pF
C81 "CL10B101KB8NNNC" 0603 8961,6366.27 r0 top value=100pF
C82 "06035A820JAT2A" 0603 2034.45,6045 r180 top value=82pF
C83 "06035A101FAT2A" 0603 6984.66,6413 r0 top value=100pF
C84 "06035A101FAT2A" 0603 8165.25,6408 r0 top value=100pF
C85 "06035A101FAT2A" 0603 7305.41,6413 r180 top value=100pF
C86 "06035A101FAT2A" 0603 8486,6408 r180 top value=100pF
C87 "06035A101FAT2A" 0603 7259.41,6814 r180 top value=100pF
C88 "06035A101FAT2A" 0603 8440,6809 r180 top value=100pF
C89 "860080675015" WCAP-ATLI_1000x1600 12772,7143 r270 top value=220uF
C90 "C0603X104K3RACTU" 0603 9733,884 r0 top value=0.1uF
C91 "C0603X104K3RACTU" 0603 9871,3034 r180 top value=0.1uF
C92 "C0603X104K3RACTU" 0603 9733.5,5029 r0 top value=0.1uF
C93 "GRM32ER7YA106KA12L" 1210_270 2915,390 r0 top value=10uF
C94 "C0603C104K5RACAUTO" 0603 2925,485 r0 top value=0.1uF
C95 "GRM32ER7YA106KA12L" 1210_270 2915,2940 r0 top value=10uF
C96 "C0603C104K5RACAUTO" 0603 2925,3035 r0 top value=0.1uF
C97 "GRM32ER7YA106KA12L" 1210_270 2705,350 r90 bottom value=10uF
C98 "GRM32ER7YA106KA12L" 1210_270 2705,2900 r90 bottom value=10uF
C99 "C0603C104K5RACAUTO" 0603 2740,360 r270 top value=0.1uF
C100 "C0603C104K5RACAUTO" 0603 2740,2910 r270 top value=0.1uF
C101 "GRM21BR61H475KE51L" 0805_HV 2625,655 r0 top value=4.7uF
C102 "GRM21BR61H475KE51L" 0805_HV 2625,3205 r0 top value=4.7uF
C103 "C0603C104K5RACAUTO" 0603 2625,735 r180 top value=0.1uF
C104 "C0603C104K5RACAUTO" 0603 2625,3285 r180 top value=0.1uF
C105 "GRM32ER7YA106KA12L" 1210_270 2610,535 r0 top value=10uF
C106 "GRM32ER7YA106KA12L" 1210_270 2610,3085 r0 top value=10uF
C107 "GRM32ER7YA106KA12L" 1210_270 3734,5465 r90 top value=10uF
C108 "C0603C104K5RACAUTO" 0603 3960,5581 r180 top value=0.1uF
C109 "C0603C104K5RACAUTO" 0603 3633,5465.5 r90 top value=0.1uF
C110 "GRM32ER7YA106KA12L" 1210_270 2915,5440 r0 top value=10uF
C111 "C0603C104K5RACAUTO" 0603 2925,5535 r0 top value=0.1uF
C112 "GRM32ER7YA106KA12L" 1210_270 2705,5400 r90 bottom value=10uF
C113 "C0603C104K5RACAUTO" 0603 2740,5410 r270 top value=0.1uF
C114 "GRM21BR61H475KE51L" 0805_HV 2625,5705 r0 top value=4.7uF
C115 "C0603C104K5RACAUTO" 0603 2625,5785 r180 top value=0.1uF
C116 "GRM32ER7YA106KA12L" 1210_270 2610,5585 r0 top value=10uF
C117 "C0603C105K3RACTU" 0603 10687.61,6432.04 r90 top value=1uF
C118 "CL10B101KB8NNNC" 0603 10930.61,6419.04 r90 top value=100pF
C119 "GRM188R61H474KA12D" 0603 13026,6785.5 r90 top value=0.47uF
C120 "B32921C3683K" B32921_12mm 7657.45,5853 r90 top value=0.068uF
C121 "B32921C3683K" B32921_12mm 7657.45,3796.94 r90 top value=0.068uF
C122 "B32921C3683K" B32921_12mm 7657.45,1740.87 r90 top value=0.068uF
C123 "GCM32DC72A475KE02L" 1210_220 13405,7184 r180 top value=4.7uF
C124 "GRM21BR72A473KA01L" 0805_HV 13422,7072 r180 top value=0.047uF
C125 "GRM21BR61H475KE51L" 0805_HV 13614,6744 r0 top value=4.7uF
C126 "875105444004" WCAP-PSLP_630x580 12741,6596 r90 top value=33uF
C127 "B32921C3683K" B32921_12mm 6340.02,4293.99 r0 top value=0.068uF
C128 "B32921C3683K" B32921_12mm 6489.02,181.87 r0 top value=0.068uF
C129 "B32921C3683K" B32921_12mm 6340.02,2237.93 r0 top value=0.068uF
C130 "CK45-B3FD222KYVNA" CAPRD1000W60D900H1200 5311,6947.1 r180 top value=2200pF
C131 "C0603X104K3RACTU" 0603 9380.7,6333.75 r90 top value=0.1uF
C132 "C0603X104K3RACTU" 0603 9186.9,6333.75 r90 top value=0.1uF
C133 "06035A101FAT2A" 0603 6940,6813.93 r0 top value=100pF
C134 "C0603X104K3RACTU" 0603 6770,6883.38 r180 top value=0.1uF
C135 "C0603X104K3RACTU" 0603 6514,6280 r0 top value=0.1uF
D1 "BZV55C15-TP" MiniMELF 1283.5,3102 r0 top value=15V
D2 "BZV55C15-TP" MiniMELF 1283.5,5049 r0 top value=15V
D3 "B160-13-F" SMA 1028,3102 r180 top value=60V
D4 "BZV55C15-TP" MiniMELF 1283.5,7265 r0 top value=15V
D5 "BZV55C15-TP" MiniMELF 1283.5,1480 r0 top value=15V
D6 "B160-13-F" SMA 1028,5049 r180 top value=60V
D7 "B160-13-F" SMA 1028,7265 r180 top value=60V
D8 "B160-13-F" SMA 1028,1480 r180 top value=60V
D9 "B0520LW-7-F" SOD-123 2925,275 r0 top value=20V
D11 "B0520LW-7-F" SOD-123 2925,2825 r0 top value=20V
D12 "MMBZ27VALT1G" SOT-23 1868,1052 r180 bottom value=27V
D13 "MMBZ33VALT1G" SOT-23 1868,1052 r180 top value=33V
D14 "MMBZ27VALT1G" SOT-23 1868,3602 r180 bottom value=27V
D15 "MMBZ33VALT1G" SOT-23 1868,3602 r180 top value=33V
D16 "MMBZ27VALT1G" SOT-23 1868,6102 r180 bottom value=27V
D17 "MMBZ33VALT1G" SOT-23 1868,6102 r180 top value=33V
D18 "150060VS55040" WL-SMCD-0603 11464,6614 r180 top value=Green
D19 "150060VS55040" WL-SMCD-0603 10224,6815 r90 top value=Green
D24 "B0520LW-7-F" SOD-123 2925.53,565 r0 top value=20V
D25 "B0520LW-7-F" SOD-123 2925.53,3115 r0 top value=20V
D26 "150060VS55040" WL-SMCD-0603 2385,646.34 r90 top value=Green
D27 "150060VS55040" WL-SMCD-0603 2385,3196.34 r90 top value=Green
D28 "MMSZ5232B-7-F" SOD-123 2485,740 r270 top value=5.6V
D29 "MMSZ5232B-7-F" SOD-123 2485,3290 r270 top value=5.6V
D30 "B0520LW-7-F" SOD-123 2925,5325 r0 top value=20V
D31 "B0520LW-7-F" SOD-123 2925.53,5615 r0 top value=20V
D32 "150060VS55040" WL-SMCD-0603 2385,5696.34 r90 top value=Green
D33 "MMSZ5232B-7-F" SOD-123 2485,5790 r270 top value=5.6V
FID1 "Fiducial" Fiducial10-30 13290,101 r0 top
FID2 "Fiducial" Fiducial10-30 528,7799 r0 top
FID3 "Fiducial" Fiducial10-30 13271,7754 r0 top
FID4 "Fiducial" Fiducial10-30 528,7799 r90 bottom
FID5 "Fiducial" Fiducial10-30 13290,101 r90 bottom
FID6 "Fiducial" Fiducial10-30 13271,7754 r90 bottom
GND_1 "5000" Keystone5000#1 1800,430.55 r90 top
GND_2 "5000" Keystone5000#1 1800,2952 r90 top
GND_3 "5000" Keystone5000#1 1800.79,5452 r90 top
H1 "MPMS 003 0005 PH" BuildingFastener_MPMS_003_0005_PH 219.45,205 r0 top locked
H2 "MPMS 003 0005 PH" BuildingFastener_MPMS_003_0005_PH 13573.7,215 r0 top locked
H3 "MPMS 003 0005 PH" BuildingFastener_MPMS_003_0005_PH 13568.7,7660 r0 top locked
H4 "MPMS 003 0005 PH" BuildingFastener_MPMS_003_0005_PH 234.45,7660 r0 top locked
H5 "24438" Keystone24438 219.45,205 r180 bottom locked
H6 "24438" Keystone24438 13573.7,215 r180 bottom locked
H7 "24438" Keystone24438 13568.7,7660 r180 bottom locked
H8 "24438" Keystone24438 234.45,7660 r180 bottom locked
H9 "MPMS 003 0005 PH" BuildingFastener_MPMS_003_0005_PH 1453,3424 r0 top locked
H10 "MPMS 003 0005 PH" BuildingFastener_MPMS_003_0005_PH 5846.54,215 r0 top
H11 "MPMS 003 0005 PH" BuildingFastener_MPMS_003_0005_PH 10722,1026 r0 top locked
H12 "MPMS 003 0005 PH" BuildingFastener_MPMS_003_0005_PH 10722.01,7660 r0 top locked
H13 "MPMS 003 0005 PH" BuildingFastener_MPMS_003_0005_PH 5846.53,7660 r0 top locked
H14 "24438" Keystone24438 1453,3424 r180 bottom locked
H15 "24438" Keystone24438 5842,215 r180 bottom
H16 "24438" Keystone24438 10722,1026 r180 bottom locked
H17 "24438" Keystone24438 10722.01,7660 r180 bottom locked
H18 "24438" Keystone24438 5846.53,7660 r180 bottom locked
H19 "OMNI-UNI-18-50" HSINK_OMNI-UNI-18-50 8629.15,4840.95 r0 bottom
H20 "OMNI-UNI-18-50" HSINK_OMNI-UNI-18-50 6655,4840.95 r0 bottom
H21 "OMNI-UNI-18-50" HSINK_OMNI-UNI-18-50 8629.15,2784.89 r0 bottom
H22 "OMNI-UNI-18-50" HSINK_OMNI-UNI-18-50 6655,2784.89 r0 bottom
H23 "OMNI-UNI-18-50" HSINK_OMNI-UNI-18-50 8629.15,728.82 r0 bottom
H24 "OMNI-UNI-18-50" HSINK_OMNI-UNI-18-50 6655,728.82 r0 bottom
J1 "74650073R" Wurth_WP-THRBU 12578.55,285.55 r0 top
J2 "74650073R" Wurth_WP-THRBU 11199,286 r0 top
J3 "74650073R" Wurth_WP-THRBU 294,2132 r270 top
J4 "74650073R" Wurth_WP-THRBU 299,4079.01 r270 top
J5 "HSEC8-160-01-L-DV-A-BL" controlCARD-120HSEC 7577.56,7432.28 r0 top locked
J6 "61300211121" WURTH_61300211121 6361,7149 r90 top
J7 "NPTC041KFXC-RC" Sullins_xPxC041KFXC-RC 9111.04,638.93 r0 top
J8 "61300211121" WURTH_61300211121 8940,7160 r180 top
J9 "NPTC041KFXC-RC" Sullins_xPxC041KFXC-RC 6219.7,2694.99 r0 top
J10 "61300211121" WURTH_61300211121 8143.33,7743 r90 top
J11 "61300211121" WURTH_61300211121 8473.7,7789 r0 top
J12 "NPTC041KFXC-RC" Sullins_xPxC041KFXC-RC 6219.7,4751.06 r0 top
J13 "HSEC8-130-01-L-DV-A" controlCARD-180HSEC-60pinAddon 9925.7,7433.14 r0 top locked
J14 "NPTC041KFXC-RC" Sullins_xPxC041KFXC-RC 8147.26,638.93 r0 top
J15 "NPTC041KFXC-RC" Sullins_xPxC041KFXC-RC 7183.48,2694.99 r0 top
J16 "NPTC041KFXC-RC" Sullins_xPxC041KFXC-RC 7183.48,4751.06 r0 top
J17 "NPTC041KFXC-RC" Sullins_xPxC041KFXC-RC 7183.48,638.93 r0 top
J18 "NPTC041KFXC-RC" Sullins_xPxC041KFXC-RC 8147.26,2694.99 r0 top
J19 "NPTC041KFXC-RC" Sullins_xPxC041KFXC-RC 8147.26,4751.06 r0 top
J20 "NPTC041KFXC-RC" Sullins_xPxC041KFXC-RC 6219.7,638.93 r0 top
J21 "NPTC041KFXC-RC" Sullins_xPxC041KFXC-RC 9111.04,2694.99 r0 top
J22 "NPTC041KFXC-RC" Sullins_xPxC041KFXC-RC 9111.04,4751.06 r0 top
J23 "NPTC082KFMS-RC" Sullins_xPxC082KFMS-RC 10092.93,688.93 r0 top
J24 "NPTC082KFMS-RC" Sullins_xPxC082KFMS-RC 10092.93,2744.99 r0 top
J25 "NPTC082KFMS-RC" Sullins_xPxC082KFMS-RC 10092.93,4801.06 r0 top
J26 "61300211121" WURTH_61300211121 12121,6280 r270 bottom
J27 "61300211121" WURTH_61300211121 9895,1215.2 r180 top
J28 "61300211121" WURTH_61300211121 12121,6534 r90 bottom
J29 "61300211121" WURTH_61300211121 9895,3271.27 r180 top
J30 "61300211121" WURTH_61300211121 9895,5327.33 r180 top
J31 "74650073R" Wurth_WP-THRBU 294,6295 r0 top
J32 "74650073R" Wurth_WP-THRBU 294,940.01 r270 top
J33 "PJ-002AH-SMT-TR" CUI_PJ-002AH-SMT 12113.41,7551.08 r270 top
J34 "61300211121" WURTH_61300211121 12422,7242 r180 top
J35 "SSW-102-01-T-S" Samtec_SSW-102-01-x-S 12580,5860 r180 top
J36 "SSW-102-01-T-S" Samtec_SSW-102-01-x-S 13620,5860 r0 top
J37 "61300211121" WURTH_61300211121 6130,7090 r180 top
J38 "PPTC041LFBN-RC" Sullins_xPxC041LFBN 11550,6042.18 r180 top
J39 "61300211121" WURTH_61300211121 11599.76,7553.05 r90 top
K1 "T9AS1D12-15" Relay_T9AS1D12 1150,2432 r180 top
K2 "T9AS1D12-15" Relay_T9AS1D12 1155,4379 r180 top
K3 "T9AS1D12-15" Relay_T9AS1D12 1150,6595 r180 top
K4 "T9AS1D12-15" Relay_T9AS1D12 1150,810 r180 top
L1 "750343810" 750343810 5000,1351 r0 bottom locked value=340uH
L2 "750343811" 750343811 2820,1350 r180 top locked
L3 "750343810" 750343810 5000,3920 r0 bottom locked value=340uH
L4 "750343811" 750343811 2820,3900 r180 top locked
L5 "750343810" 750343810 5000,6405 r0 bottom locked value=340uH
L6 "750343811" 750343811 2820,6400 r180 top locked
L7 "74279228260" 0603 2198,5360 r270 top value="26 ohm"
L8 "74279228260" 0603 2195,312.54 r270 top value="26 ohm"
L9 "74279228260" 0603 7088.7,1548.21 r270 top value="26 ohm"
L10 "74279228260" 0603 7091.08,3604.28 r270 top value="26 ohm"
L11 "742792662" 0603 2735,605 r90 top value="1000 ohm"
L12 "742792662" 0603 2735,3165 r90 top value="1000 ohm"
L13 "74279228260" 0603 2197,2860 r270 top value="26 ohm"
L14 "74279228260" 0603 7090.08,5659.86 r270 top value="26 ohm"
L15 "742792662" 0603 2735,5656 r90 top value="1000 ohm"
L16 "7447709220" WE-PD_1210 13225.18,6468 r180 top value=22uH
L17 "74279228260" 0603 9138,6937 r180 top value="26 ohm"
L19 "74279221111" 1206 11239.7,7367 r180 top value="110 ohm"
L21 "74279228260" 0603 6760.41,6606 r270 top value="26 ohm"
L23 "74279228260" 0603 7941,6595 r270 top value="26 ohm"
LBL1 "THT-14-423-10" Label_650x200 4985.24,144.63 r0 top
LOGO1 "CE Mark" CE_Mark_5mm 10223,179 r0 top
Logo2 "Pb-Free Symbol" Pb-Free_Overlay_Medium 6063.24,7345.64 r0 top
Logo3 "FCC disclaimer" FCC_disclaimer 5106.45,8660 r0 top
Logo4 "CAUTION.  READ USER GUIDE BEFORE USE" IEC_Caution_Medium 4750,6680 r0 top
Logo5 "ESD Susceptible" ESD_Overlay_Medium 5140,7350 r0 top
LOGO6 "CAUTION HOT SURFACE" IEC_HotSurface_Medium 8455,3793.55 r0 top
LOGO7 "DANGER HIGH VOLTAGE" IEC_HighVoltage_Medium 11931,366.55 r0 top
LOGO8 "DANGER HIGH VOLTAGE" IEC_HighVoltage_Medium 295,5643 r0 top
LOGO9 "DANGER HIGH VOLTAGE" IEC_HighVoltage_Medium 284.45,3470 r0 top
LOGO10 "DANGER HIGH VOLTAGE" IEC_HighVoltage_Medium 301,1557 r0 top
LOGO11 "CAUTION HOT SURFACE" IEC_HotSurface_Medium 8460,5590 r0 top
LOGO12 "CAUTION HOT SURFACE" IEC_HotSurface_Medium 8450,1690 r0 top
LOGO13 "DANGER HIGH VOLTAGE" IEC_HighVoltage_Medium 13150,5970 r0 top
Logo14 "WEEE logo" WEEE_Minimum 4490,257 r0 top
Q1 "C3M0075120D" FP-C3M0075120D_TO-247-3-MFG 7182.48,900.56 r270 bottom
Q2 "C3M0075120D" FP-C3M0075120D_TO-247-3-MFG 6218.7,900.56 r270 bottom
Q3 "C3M0060065D" FP-C3M0060065D_TO-247-3-MFG 8146.26,900.56 r270 bottom
Q4 "C3M0060065D" FP-C3M0060065D_TO-247-3-MFG 9110.04,900.56 r270 bottom
Q5 "C3M0075120D" FP-C3M0075120D_TO-247-3-MFG 7182.48,2956.63 r270 bottom
Q6 "C3M0075120D" FP-C3M0075120D_TO-247-3-MFG 6218.7,2956.63 r270 bottom
Q7 "C3M0060065D" FP-C3M0060065D_TO-247-3-MFG 8146.26,2956.63 r270 bottom
Q8 "C3M0060065D" FP-C3M0060065D_TO-247-3-MFG 9110.04,2956.63 r270 bottom
Q9 "C3M0075120D" FP-C3M0075120D_TO-247-3-MFG 7182.48,5012.69 r270 bottom
Q10 "C3M0075120D" FP-C3M0075120D_TO-247-3-MFG 6218.7,5012.69 r270 bottom
Q11 "C3M0060065D" FP-C3M0060065D_TO-247-3-MFG 8146.26,5012.69 r270 bottom
Q12 "C3M0060065D" FP-C3M0060065D_TO-247-3-MFG 9110.04,5012.69 r270 bottom
Q13 "CSD18534Q5A" DQJ0008A 11927.24,6281 r0 top value=60V
Q14 "CSD18534Q5A" DQJ0008A 11928,6597.75 r0 top value=60V
Q15 "NDT3055L" SOT-223 731,3217 r270 top value=60V
Q16 "NDT3055L" SOT-223 731,5163 r270 top value=60V
Q17 "NDT3055L" SOT-223 731,7380 r270 top value=60V
Q18 "NDT3055L" SOT-223 661,1529 r270 top value=60V
R1 "CRCW2010510KJNEF" 2010 12870.7,5392.45 r180 bottom value=510k
R2 "CRCW2010510KJNEF" 2010 12873.7,4874.55 r180 bottom value=510k
R3 "CRCW2010510KJNEF" 2010 13170.7,5392.45 r180 bottom value=510k
R4 "CRCW2010510KJNEF" 2010 13173.7,4874.55 r180 bottom value=510k
R5 "PSR400ITQFJ2L00" FP-PSR400ITQFJ2L00_3921-MFG 2034.45,1350 r180 top value=2m
R6 "CRCW2010510KJNEF" 2010 13470.7,5392.45 r180 bottom value=510k
R7 "CRCW2010510KJNEF" 2010 13473.7,4874.55 r180 bottom value=510k
R8 "ERJ-3EKF1002V" 0603 10221.29,2893.12 r0 bottom value=10.0k
R9 "CRCW2010510KJNEF" 2010 11843.85,4882.55 r0 bottom value=510k
R10 "CRCW2010510KJNEF" 2010 11843.85,5314.45 r0 bottom value=510k
R11 "ERJ-3EKF1002V" 0603 10221.29,4949.18 r0 bottom value=10.0k
R12 "CRCW2010510KJNEF" 2010 11543.85,4882.55 r0 bottom value=510k
R13 "CRCW2010510KJNEF" 2010 11543.85,5314.45 r0 bottom value=510k
R14 "CRCW2010510KJNEF" 2010 11243.85,4882.55 r0 bottom value=510k
R15 "CRCW2010510KJNEF" 2010 11243.85,5314.45 r0 bottom value=510k
R16 "SQMW7R68J" SQM_7 4710,2120 r90 top locked value=0.68
R17 "SQMW7R68J" SQM_7 4710,4680 r90 top locked value=0.68
R18 "SQMW7R68J" SQM_7 4710,7170 r90 top locked value=0.68
R19 "ERJ-PB3B1003V" FP-ERJ-PB3B1003V_0603-MFG 6665.35,1921.06 r90 bottom value=100k
R20 "ERJ-PB3B1003V" FP-ERJ-PB3B1003V_0603-MFG 6715.28,1921.06 r90 bottom value=100k
R21 "ERJ-PB3B1003V" FP-ERJ-PB3B1003V_0603-MFG 6670,3980 r90 bottom value=100k
R22 "ERJ-PB3B1003V" FP-ERJ-PB3B1003V_0603-MFG 6719.93,3980 r90 bottom value=100k
R23 "ERJ-PB3B1003V" FP-ERJ-PB3B1003V_0603-MFG 6980,5810 r0 top value=100k
R24 "ERJ-PB3B1003V" FP-ERJ-PB3B1003V_0603-MFG 6980,5870 r0 top value=100k
R25 "CRCW0603100KFKEA" 0603 8820.7,6674 r90 top value=100k
R26 "CRCW0603100KFKEA" 0603 9380.7,6679 r90 top value=100k
R27 "CRCW060368R1FKEA" 0603 8820.7,6814 r90 top value=68.1
R28 "CRCW060368R1FKEA" 0603 9380,6812 r90 top value=68.1
R29 "CRCW0603100KFKEA" 0603 8885.7,6544 r90 top value=100k
R30 "CRCW0603100KFKEA" 0603 9315.7,6549 r90 top value=100k
R31 "CRCW0603100KFKEA" 0603 8961.3,6303.27 r180 top value=100k
R32 "ERJ-3EKF1002V" 0603 10221.29,837.06 r0 bottom value=10.0k
R33 "CRCW0603100KFKEA" 0603 9091,6366.27 r180 top value=100k
R34 "RCS06030000Z0EA" 0603 7702,7168 r90 top value=0
R35 "CRCW08053K30JNEA" 0805_HV 7985.33,7753 r180 top value=3.3k
R36 "RCS06030000Z0EA" 0603 7948.7,7168 r90 top value=0
R37 "ERJ-3EKF1002V" 0603 7985.63,7669 r180 top value=10.0k
R38 "CRCW060368R1FKEA" 0603 7992.33,7825 r0 top value=68.1
R39 "RG2012P-113-B-T5" 0805_HV 6973.41,6335 r0 top value=11.0k
R40 "CRCW060368R1FKEA" 0603 8856,6336.27 r90 top value=68.1
R41 "PSR400ITQFJ2L00" FP-PSR400ITQFJ2L00_3921-MFG 2034.45,3900 r180 top value=2m
R42 "RT0805BRD071ML" 0805_HV 137.45,2637 r90 top value=1.00Meg
R43 "RT0805BRD071ML" 0805_HV 137.45,2797 r90 top value=1.00Meg
R44 "RT0805BRD071ML" 0805_HV 137.45,2957 r90 top value=1.00Meg
R45 "RT0805BRD071KL" 0805_HV 137.45,3117 r90 top value=1.00k
R46 "CRCW060368R1FKEA" 0603 6860.11,6366 r90 top value=68.1
R47 "PSR400ITQFJ2L00" FP-PSR400ITQFJ2L00_3921-MFG 2034.45,6400 r180 top value=2m
R48 "RT0805BRD071ML" 0805_HV 388,2637 r90 top value=1.00Meg
R49 "RT0805BRD071ML" 0805_HV 388,2797 r90 top value=1.00Meg
R50 "RT0805BRD071ML" 0805_HV 388,2957 r90 top value=1.00Meg
R51 "RT0805BRD071KL" 0805_HV 388,3117 r90 top value=1.00k
R52 "ERJ-3EKF1002V" 0603 9870,1049.2 r0 top value=10.0k
R53 "ERJ-3GEY0R00V" 0603 3960,593 r0 top value=0
R54 "CRCW0402100KFKED" 0402 13704,6857 r0 top value=100k
R55 "ERJ-3EKF1002V" 0603 9718.5,1215.2 r180 top value=10.0k
R56 "RG2012P-113-B-T5" 0805_HV 7099.11,6366 r90 top value=11.0k
R57 "CRCW04029K09FKED" 0402 13626,6880 r270 top value=9.09k
R58 "ERJ-3EKF1002V" 0603 9870,1113.75 r0 top value=10.0k
R59 "CRCW0805200RFKEA" 0805_HV 11640.79,6266 r270 top value=200
R60 "ERJ-3EKF1002V" 0603 11729.25,6267.25 r270 top value=10.0k
R61 "RG2012P-113-B-T5" 0805_HV 7318,6323 r180 top value=11.0k
R62 "ERJ-3EKF1002V" 0603 9870,3105.27 r0 top value=10.0k
R63 "ERJ-3GEY0R00V" 0603 3960,3143 r0 top value=0
R64 "ERJ-3EKF1002V" 0603 9720,3240 r270 top value=10.0k
R65 "ERJ-3EKF1002V" 0603 9870,3166.27 r0 top value=10.0k
R66 "CRCW0805200RFKEA" 0805_HV 11626.54,6583.76 r270 top value=200
R67 "RT0805BRD071ML" 0805_HV 142.45,4604 r90 top value=1.00Meg
R68 "RT0805BRD071ML" 0805_HV 142.45,4764 r90 top value=1.00Meg
R69 "RT0805BRD071ML" 0805_HV 142.45,4924 r90 top value=1.00Meg
R70 "RT0805BRD071KL" 0805_HV 142.45,5084 r90 top value=1.00k
R71 "CRCW060368R1FKEA" 0603 7427.11,6366 r90 top value=68.1
R72 "CRCW0805330RJNEA" 0805_HV 11959.7,6967 r270 top value=330
R73 "RT0805BRD071ML" 0805_HV 393.01,4764 r90 top value=1.00Meg
R74 "RT0805BRD071ML" 0805_HV 393,4924 r90 top value=1.00Meg
R75 "RT0805BRD071KL" 0805_HV 393,5084 r90 top value=1.00k
R76 "ERJ-3EKF1002V" 0603 11715,6583 r270 top value=10.0k
R77 "ERJ-3EKF1002V" 0603 9870,5161.33 r0 top value=10.0k
R78 "RG2012P-113-B-T5" 0805_HV 7188.11,6367 r90 top value=11.0k
R79 "RG2012P-113-B-T5" 0805_HV 7272.41,6895 r180 top value=11.0k
R80 "RT0805BRD071ML" 0805_HV 134.45,6761 r90 top value=1.00Meg
R81 "RT0805BRD071ML" 0805_HV 134.45,6921 r90 top value=1.00Meg
R82 "RT0805BRD071ML" 0805_HV 134.45,7081 r90 top value=1.00Meg
R83 "RT0805BRD071KL" 0805_HV 134.45,7241 r90 top value=1.00k
R84 "CRCW060368R1FKEA" 0603 7383,6843 r90 top value=68.1
R85 "RT0805BRD071ML" 0805_HV 388,6764 r90 top value=1.00Meg
R86 "RT0805BRD071ML" 0805_HV 388,6924 r90 top value=1.00Meg
R87 "RT0805BRD071ML" 0805_HV 388,7084 r90 top value=1.00Meg
R88 "RT0805BRD071KL" 0805_HV 388,7244 r90 top value=1.00k
R89 "RG2012P-113-B-T5" 0805_HV 7146.41,6861 r270 top value=11.0k
R90 "ERJ-3GEY0R00V" 0603 3960,326 r0 top value=0
R91 "ERJ-3EKF1002V" 0603 9718.5,5327.33 r180 top value=10.0k
R92 "ERJ-3EKF1002V" 0603 9870,5225.87 r0 top value=10.0k
R93 "ERJ-3EKF1002V" 0603 6359,6912 r90 top value=10.0k
R94 "RG2012P-113-B-T5" 0805_HV 8154,6330 r0 top value=11.0k
R95 "RT0805BRD071ML" 0805_HV 1795,2030 r90 top value=1.00Meg
R96 "RT0805BRD071ML" 0805_HV 1795,2180 r90 top value=1.00Meg
R97 "RT0805BRD071ML" 0805_HV 1795,2330 r90 top value=1.00Meg
R98 "RT0805BRD071KL" 0805_HV 1795,2480 r90 top value=1.00k
R99 "CRCW060368R1FKEA" 0603 8038.7,6336 r90 top value=68.1
R100 "RT0805BRD071ML" 0805_HV 2025,2030 r90 top value=1.00Meg
R101 "RT0805BRD071ML" 0805_HV 2025,2180 r90 top value=1.00Meg
R102 "RT0805BRD071ML" 0805_HV 2025,2330 r90 top value=1.00Meg
R103 "RT0805BRD071KL" 0805_HV 2025,2480 r90 top value=1.00k
R104 "RG2012P-113-B-T5" 0805_HV 8279.7,6361 r90 top value=11.0k
R105 "RG2012P-113-B-T5" 0805_HV 8496,6330 r180 top value=11.0k
R106 "RT0805BRD071ML" 0805_HV 1746.45,4499 r90 top value=1.00Meg
R107 "RT0805BRD071ML" 0805_HV 1746.45,4659 r90 top value=1.00Meg
R108 "RT0805BRD071ML" 0805_HV 1746.45,4819 r90 top value=1.00Meg
R109 "RT0805BRD071KL" 0805_HV 1746.45,4979 r90 top value=1.00k
R110 "RT0805BRD071ML" 0805_HV 393,4604 r90 top value=1.00Meg
R111 "CRCW060368R1FKEA" 0603 8607.7,6361 r90 top value=68.1
R112 "RT0805BRD071ML" 0805_HV 1997,4499 r90 top value=1.00Meg
R113 "RT0805BRD071ML" 0805_HV 1997,4659 r90 top value=1.00Meg
R114 "RT0805BRD071ML" 0805_HV 1997,4819 r90 top value=1.00Meg
R115 "RT0805BRD071KL" 0805_HV 1997,4979 r90 top value=1.00k
R116 "RG2012P-113-B-T5" 0805_HV 8368.7,6362 r90 top value=11.0k
R117 "RG2012P-113-B-T5" 0805_HV 8453,6890 r180 top value=11.0k
R118 "RT0805BRD071ML" 0805_HV 1791.06,6863 r90 top value=1.00Meg
R119 "RT0805BRD071ML" 0805_HV 1791.06,7023 r90 top value=1.00Meg
R120 "RT0805BRD071ML" 0805_HV 1791.06,7183 r90 top value=1.00Meg
R121 "RT0805BRD071KL" 0805_HV 1791.06,7343 r90 top value=1.00k
R122 "CRCW060368R1FKEA" 0603 8567.7,6873 r90 top value=68.1
R123 "RT0805BRD071ML" 0805_HV 2041.61,6863 r90 top value=1.00Meg
R124 "RT0805BRD071ML" 0805_HV 2041.61,7023 r90 top value=1.00Meg
R125 "RT0805BRD071ML" 0805_HV 2041.61,7183 r90 top value=1.00Meg
R126 "RT0805BRD071KL" 0805_HV 2041.61,7343 r90 top value=1.00k
R127 "RG2012P-113-B-T5" 0805_HV 8327,6856 r270 top value=11.0k
R128 "RG1608P-103-B-T5" 0603 9313.74,6333.75 r90 top value=10.0k
R129 "CRCW060310R0JNEA" 0603 9347.71,6435.2 r0 top value=10
R130 "RG1608P-103-B-T5" 0603 9250.46,6333.75 r270 top value=10.0k
R131 "RG2012P-113-B-T5" 0805_HV 6920,6895 r0 top value=11.0k
R132 "RT0805BRD071ML" 0805_HV 13406,2957.45 r90 bottom value=1.00Meg
R133 "RT0805BRD071ML" 0805_HV 13406,3117.45 r90 bottom value=1.00Meg
R134 "RT0805BRD071ML" 0805_HV 13406,3277.45 r90 bottom value=1.00Meg
R135 "RT0805BRD071KL" 0805_HV 13406,3437.45 r90 bottom value=1.00k
R136 "CRCW060368R1FKEA" 0603 6770,6813.43 r180 top value=68.1
R137 "RT0805BRD071ML" 0805_HV 13656.55,2957.45 r90 bottom value=1.00Meg
R138 "RT0805BRD071ML" 0805_HV 13656.55,3117.45 r90 bottom value=1.00Meg
R139 "RG1608P-103-B-T5" 0603 8217.7,6938 r180 top value=10.0k
R140 "CRCW060310R0JNEA" 0603 8117.7,6838 r90 top value=10
R141 "RG1608P-103-B-T5" 0603 8217.7,6873 r0 top value=10.0k
R142 "RG1608P-103-B-T5" 0603 6390,6563.5 r90 top value=10.0k
R143 "CRCW060310R0JNEA" 0603 6623.77,6430 r270 top value=10
R144 "RG1608P-103-B-T5" 0603 6490,6594.33 r0 top value=10.0k
R145 "CRCW0603105RFKEA" 0603 2064.45,1120 r270 top value=105
R146 "RC0603FR-0733RL" 0603 1955,320 r270 top value=33.0
R147 "CRCW0603105RFKEA" 0603 1999.45,1120 r270 top value=105
R148 "CRCW0603105RFKEA" 0603 2064.45,3670 r270 top value=105
R149 "RC0603FR-0733RL" 0603 1955,2870 r270 top value=33.0
R150 "CRCW0603105RFKEA" 0603 1999.45,3670 r270 top value=105
R151 "CRCW0603105RFKEA" 0603 2064.45,6170 r270 top value=105
R152 "RC0603FR-0733RL" 0603 1955,5370 r270 top value=33.0
R153 "CRCW0603105RFKEA" 0603 1999.45,6170 r270 top value=105
R154 "ERJ-3GEY0R00V" 0603 3960,2876 r0 top value=0
R155 "ERJ-3GEY0R00V" 0603 2625,805 r180 top value=0
R156 "RC0603FR-07820RL" 0603 2385,775 r90 top value=820
R157 "ERJ-3GEY0R00V" 0603 2625,3355 r180 top value=0
R158 "RC0603FR-07820RL" 0603 2385,3325 r90 top value=820
R159 "ERJ-3GEY0R00V" 0603 3960,5643 r0 top value=0
R160 "ERJ-3GEY0R00V" 0603 3960,5376 r0 top value=0
R161 "ERJ-3GEY0R00V" 0603 2625,5855 r180 top value=0
R162 "RC0603FR-07820RL" 0603 2385,5825 r90 top value=820
R163 "RCS06030000Z0EA" 0603 8330,7168 r90 top value=0
R164 "RCS06030000Z0EA" 0603 8420,7169 r90 top value=0
R165 "RCS06030000Z0EA" 0603 8513,7169 r90 top value=0
R166 "RT0805BRD071ML" 0805_HV 13656.55,3277.45 r90 bottom value=1.00Meg
R167 "ERJ-3EKF1002V" 0603 10430,5000 r180 top value=10.0k
R168 "CRCW120610K0JNEA" 1206 6950,800 r0 top value=10k
R169 "CRCW120610K0JNEA" 1206 6950,2860 r0 top value=10k
R170 "CRCW120610K0JNEA" 1206 6950,4910 r0 top value=10k
R171 "CRCW120610K0JNEA" 1206 8880,800 r0 top value=10k
R172 "CRCW120610K0JNEA" 1206 7910,800 r180 top value=10k
R173 "CRCW120610K0JNEA" 1206 8880,2860 r0 top value=10k
R174 "CRCW120610K0JNEA" 1206 7910,2860 r180 top value=10k
R175 "CRCW120610K0JNEA" 1206 8880,4910 r0 top value=10k
R176 "CRCW120610K0JNEA" 1206 7910,4910 r180 top value=10k
R177 "ERJ-6GEY0R00V" 0805_HV 10816.61,6315.04 r180 top value=0
R178 "CRCW060310R0JNEA" 0603 8335.97,6248.38 r180 top value=10
R179 "CRCW060310R0JNEA" 0603 6660,6330 r180 top value=10
R180 "CRCW2010510KJNEF" 2010 12870.7,1567.97 r180 bottom value=510k
R181 "CRCW2010510KJNEF" 2010 12873.7,1050.07 r180 bottom value=510k
R182 "CRCW2010510KJNEF" 2010 13170.7,1567.97 r180 bottom value=510k
R183 "CRCW2010510KJNEF" 2010 13173.7,1050.07 r180 bottom value=510k
R184 "CRCW2010510KJNEF" 2010 13470.7,1567.97 r180 bottom value=510k
R185 "CRCW2010510KJNEF" 2010 13473.7,1050.07 r180 bottom value=510k
R186 "CRCW2010510KJNEF" 2010 11843.85,1489.97 r0 bottom value=510k
R187 "CRCW2010510KJNEF" 2010 11843.85,1058.07 r0 bottom value=510k
R188 "CRCW2010510KJNEF" 2010 11543.85,1489.97 r0 bottom value=510k
R189 "CRCW2010510KJNEF" 2010 11543.85,1058.07 r0 bottom value=510k
R190 "CRCW2010510KJNEF" 2010 11243.85,1489.97 r0 bottom value=510k
R191 "CRCW2010510KJNEF" 2010 11243.85,1058.07 r0 bottom value=510k
R192 "CRCW120610K0JNEA" 1206 5990,800 r0 top value=10k
R193 "CRCW120610K0JNEA" 1206 5990,2860 r0 top value=10k
R194 "CRCW120610K0JNEA" 1206 5990,4910 r0 top value=10k
R195 "ERJ-6GEY0R00V" 0805_HV 6939.55,7140 r270 top value=0
R196 "ERJ-6GEY0R00V" 0805_HV 7224,7640 r0 bottom value=0
R197 "ESR03EZPJ101" 0603 794,3502 r180 top value=100
R198 "ESR03EZPJ101" 0603 794,5444 r180 top value=100
R199 "ESR03EZPJ101" 0603 794,7659 r180 top value=100
R200 "ESR03EZPJ101" 0603 949,1644 r180 top value=100
R201 "CRCW06032K00JNEA" 0603 731,3436 r0 top value=2.0k
R202 "CRCW06032K00JNEA" 0603 731,7596 r0 top value=2.0k
R203 "CRCW06032K00JNEA" 0603 848,1612 r90 top value=2.0k
R204 "CRCW06032K00JNEA" 0603 731,5380 r0 top value=2.0k
R205 "RT0805BRD071KL" 0805_HV 13656.55,3437.45 r90 bottom value=1.00k
R206 "RG2012P-113-B-T5" 0805_HV 7056.41,6861 r270 top value=11.0k
R207 "RC0603FR-07820RL" 0603 11400,6685 r180 top value=820
R208 "RC0603FR-07820RL" 0603 10224,6943 r90 top value=820
RF1 "EMC2-47RKI" EMC2 1140,2010 r0 bottom value=47
RF2 "EMC2-47RKI" EMC2 1145,3957 r0 bottom value=47
RF3 "EMC2-47RKI" EMC2 1140,6173 r0 bottom value=47
RF4 "EMC2-47RKI" EMC2 1140,388 r0 bottom value=47
T1 "750313638" Wurth_750313638 3316,421 r180 top value=340uH
T2 "750313638" Wurth_750313638 3316,2971 r180 top value=340uH
T3 "750313638" Wurth_750313638 3316,5471 r180 top value=340uH
TP1 "5000" Keystone5000#1 11077,6388 r180 top
TP2 "5002" Keystone5002 11681,7799 r90 top
TP3 "5002" Keystone5002 11379,7741 r90 top
TP4 "5000" Keystone5000#1 5750,550 r90 top
TP5 "5000" Keystone5000#1 7660,550 r90 top
TP6 "5000" Keystone5000#1 9530,550 r90 top
TP7 "5000" Keystone5000#1 5750,2600 r90 top
TP8 "5000" Keystone5000#1 7660,2600 r90 top
TP9 "5000" Keystone5000#1 9530,2600 r90 top
TP10 "5000" Keystone5000#2 5750,4660 r90 top
TP11 "5000" Keystone5000#1 7660,4660 r90 top
TP12 "5000" Keystone5000#1 9530,4660 r90 top
TP13 "5000" Keystone5000#1 2200,1990 r90 top
TP14 "5000" Keystone5000#1 2200,4459 r90 top
TP15 "5000" Keystone5000#1 2249.76,6821.26 r90 top
U1 "AMC1306M05DWVR" DWV0008A 2034.45,680 r270 top
U2 "SN6505BDBVR" DBV0006A_L 3919,425 r0 top
U3 "CASR 15-NP" CASR 6523.64,1620 r180 top
U4 "CASR 15-NP" CASR 6528.29,3678.94 r180 top
U5 "AMC1306M05DWVR" DWV0008A 2034.45,3230 r270 top
U6 "CASR 15-NP" CASR 6523.94,5730 r180 top
U7 "SN6505BDBVR" DBV0006A_L 3919,2975 r0 top
U8 "AMC1306M05DWVR" DWV0008A 2034.45,5730 r270 top
U9 "OPA4340UA" D0014A_N 9099.7,6605.17 r270 top
U10 "TLV70450DBVR" DBV0005A_N 2615,390 r180 top
U11 "LM76003RNPR" RNP0030B 13452.63,6901.15 r90 top
U12 "PTH08080WAZT" EUG0005A 11584.7,6982 r0 top
U13 "LMT87LPM" LP0003A 9663.54,977.94 r90 bottom
U14 "LMT87LPM" LP0003A 9663.54,3034 r90 bottom
U15 "TLV1117LV33DCYR" DCY0004A_N 10574.7,6855.19 r90 top
U16 "LMT87LPM" LP0003A 9664.61,5122.01 r90 bottom
U17 "LMT87QDCKRQ1" DCK0005A_N 6484,6897 r0 top
U18 "OPA4350UA" D0014A_N 7116.24,6610.17 r90 top
U19 "OPA4350UA" D0014A_N 8296.83,6605.17 r90 top
U20 "OPA340NA/250" DBV0005A_N 6510,6410 r270 top
U21 "TLV70450DBVR" DBV0005A_N 2615,2940 r180 top
U22 "SN6505BDBVR" DBV0006A_L 3919,5475 r0 top
U23 "TLV70450DBVR" DBV0005A_N 2615,5440 r180 top
U24 "REF2033AIDDCR" DDC0005A_N 10811.61,6427.04 r180 top
ZZ1 "This Assembly Note is for PCB labels only" AssemblyNoteLabel 158.45,8341 r0 top
ZZ2 "These assemblies are ESD sensitive, ESD precautions shall be observed." AssemblyNote 158.45,8232.11 r0 top
ZZ3 "These assemblies must be clean and free from flux and all contaminants. Use of no clean flux is not acceptable." AssemblyNote 158.45,8143.56 r0 top
ZZ4 "These assemblies must comply with workmanship standards IPC-A-610 Class 2, unless otherwise specified." AssemblyNote 158.45,8055 r0 top

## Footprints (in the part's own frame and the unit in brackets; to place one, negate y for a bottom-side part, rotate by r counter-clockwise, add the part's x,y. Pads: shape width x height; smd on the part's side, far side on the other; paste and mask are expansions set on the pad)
0402 [mm] "0402 from SM-752 data"
  rect 0.8x0.6 smd: 1(-0.6,0) 2(0.6,0)
  silkscreen extent -1.22,-0.52 1.22,0.52, body extent -0.55,-0.3 0.55,0.3, height 0.6
0603 [mm] "0603 from SM-752 data"
  rect 1x0.95 smd: 1(-0.8,0) 2(0.8,0)
  silkscreen extent -1.52,-0.69 1.52,0.69, body extent -0.87,-0.47 0.87,0.47, height 1
0805_HV [mil] "0805 with 30mil clearance between pads"
  rect 50x63 smd: 1(-40,0) 2(40,0)
  silkscreen extent -74,-40 74,40, body extent -43,-29 43,29, height 57
1206 [mm] "1206 from SM-752 data"
  rect 1.3x1.85 smd: 1(-1.45,0) 2(1.45,0)
  silkscreen extent -2.4,-1.21 2.4,1.21, body extent -1.7,-0.9 1.7,0.9, height 1.35
1206_180 [mm] "1206_180"
  rect 1.1x1.6 smd: 1(-1.7,0) 2(1.7,0)
  silkscreen extent -0.9,-1 0.9,1, body extent -1.75,-0.95 1.75,0.95, height 1.8
1210_220 [mm] "1210"
  rect 1.3x2.7 smd: 1(-1.45,0) 2(1.45,0)
  silkscreen extent -2.32,-1.57 2.32,1.57, body extent -1.7,-1.35 1.7,1.35, height 2.2
1210_270 [mm] "1210"
  rect 1.3x2.7 smd: 1(-1.45,0) 2(1.45,0)
  silkscreen extent -2.32,-1.57 2.32,1.57, body extent -1.7,-1.35 1.7,1.35, height 2.7
2010 [mm] "Chip Capacitor, Body 5.08x2.54mm, IPC Medium Density"
  rect 1.6x2.7 smd: 1(-2.3,0) 2(2.3,0)
  silkscreen extent -3.42,-1.65 3.42,1.65, body extent -2.73,-1.45 2.73,1.45, height 1.66
750343810 [mm] "TH, 2-Leads, Dia 66.04mm"
  oval 8.25x2.4 hole 1.6 slot 5.5 at 0 deg: 1(-9,0) 2(9,0)
  body extent -55.12,-33.01 10.92,33.02, height 39.88
750343811 [mm] "TH, 2-Leads, Body 25x42mm"
  oval 7.5x2.7 hole 1.8 slot 5 at 0 deg: 1(-9.2,0) 2(9.2,0)
  body extent -12.5,-23 12.5,23, height 44
AssemblyNote [mil] "Assembly Note"
AssemblyNoteLabel [mil] "Assembly Note for PCB Labels"
B32921_12mm [mm] "Epcos film capacitors, 10mm spacing"
  rect 1.3x1.3 hole 0.8: 1(-5,0)
  round 1.3 hole 0.8: 2(5,0)
  silkscreen extent -6.5,-3 6.5,3, body extent -6.5,-3 6.5,3, height 12
B32926_42.5mm [mm] "Epcos film capacitors, 37.5mm spacing"
  rect 1.7x1.7 hole 1.2: 1(-18.75,0)
  round 1.7 hole 1.2: 2(18.75,0)
  silkscreen extent -20.75,-14 20.75,14, body extent -20.75,-14 20.75,14, height 42.5
BuildingFastener_MPMS_003_0005_PH [mil] "MACHINE SCREW PAN PHILLIPS M3"
  round 1 on Mech3: 0(0,0)
  body extent -118,-118 118,118, height 93
CAPRD1000W60D900H1200 [mm] "Disk, Radial Capacitor"
  round 1.35 hole 0.85: 1(-5,0) 2(5,0)
  silkscreen extent -5.3,-3.5 5.3,3.5, body extent -4.48,-3.5 4.48,3.5, height 11.99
